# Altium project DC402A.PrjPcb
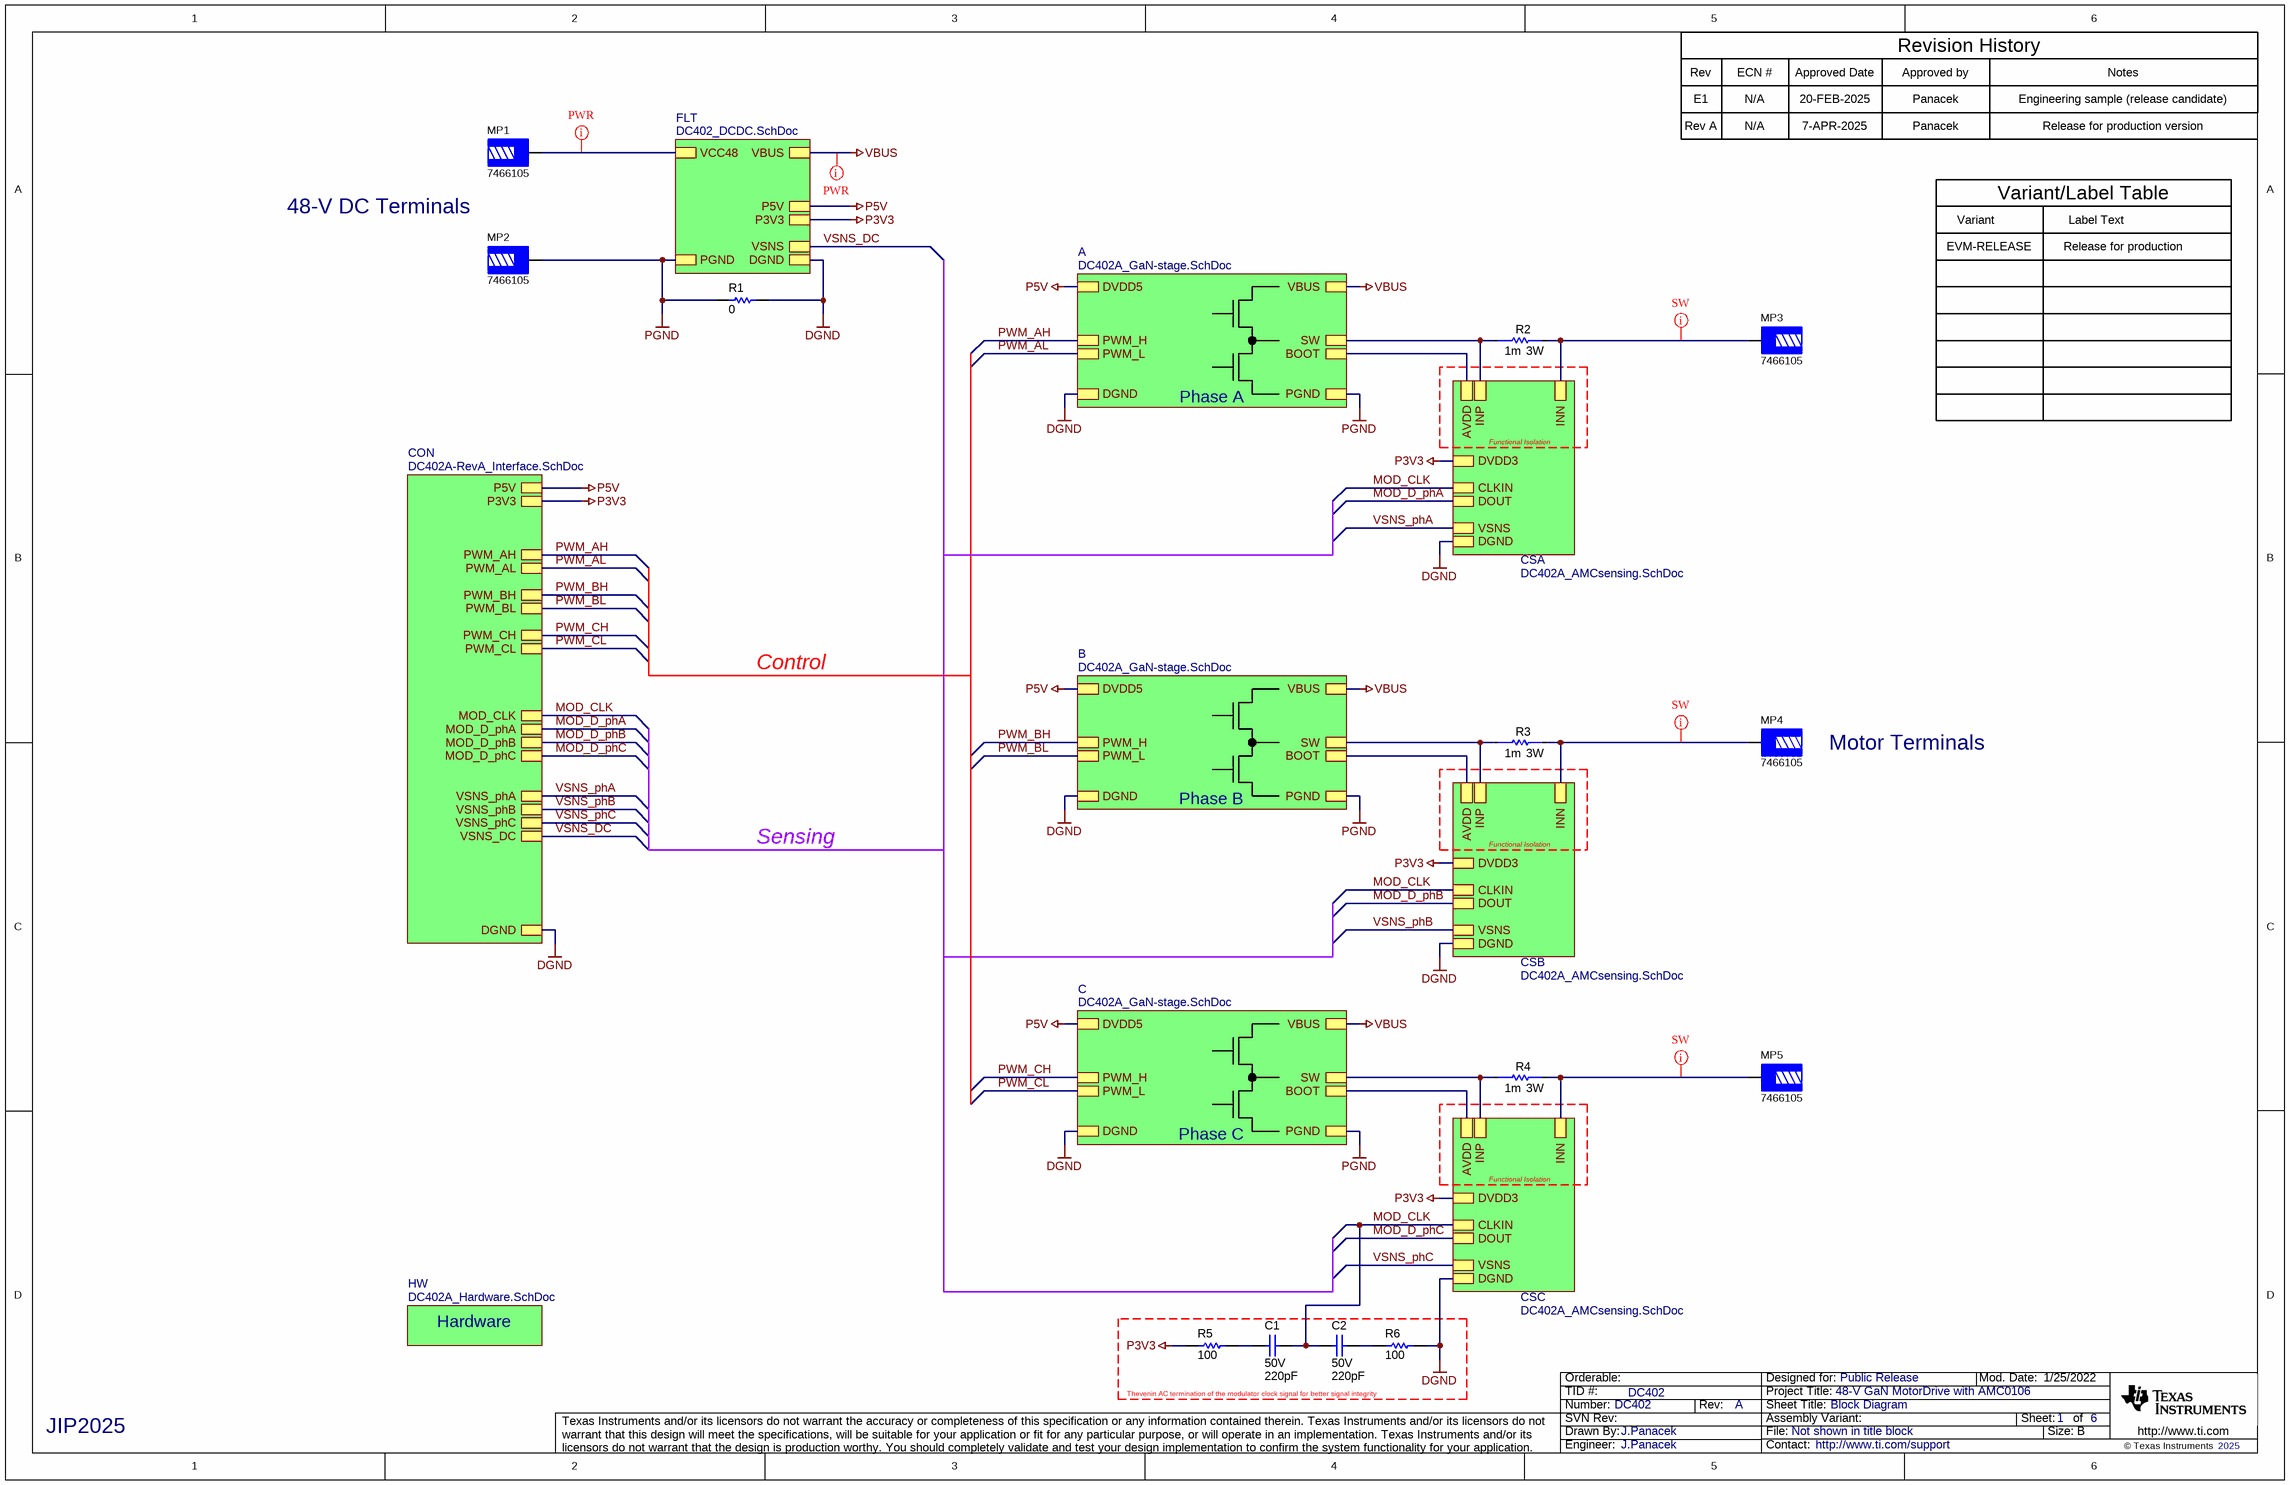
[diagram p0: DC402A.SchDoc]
CopyrightYear: 2025; PCB_Layout: J.Panacek; PCB_Rev: A; PRJ_Customer: Public Release; PRJ_Engineer: J.Panacek; PRJ_Number: DC402; PRJ_Title: 48-V GaN MotorDrive with AMC0106; SCH_Rev: A; TechSupport: http://www.ti.com/support; TID: DC402
6 sheets, 245 parts. Net scope: hierarchical (ports join the sheet entries above them; power ports are global).
Board file: DC402A.PcbDoc
Sheets:
  DC402A.SchDoc
    A = DC402A_GaN-stage.SchDoc
    CSA = DC402A_AMCsensing.SchDoc
    CON = DC402A-RevA_Interface.SchDoc
    FLT = DC402_DCDC.SchDoc
    B = DC402A_GaN-stage.SchDoc
    CSB = DC402A_AMCsensing.SchDoc
    C = DC402A_GaN-stage.SchDoc
    CSC = DC402A_AMCsensing.SchDoc
    HW = DC402A_Hardware.SchDoc

## Sheet DC402A.SchDoc: Block Diagram
size 431 x 279 mm; Date: Not shown in title block; ApprovedBy: Not shown in title block; CheckedBy: Not shown in title block; Author: Not shown in title block; CompanyName: Not shown in title block; DrawnBy: J.Panacek; Engineer: Not shown in title block; Organization: Not shown in title block; Address1: Not shown in title block; Address2: Not shown in title block; Address3: Not shown in title block; Address4: Not shown in title block; DocumentNumber: 1; Revision: Use project parameter SCH_Rev; SheetNumber: 1; SheetTotal: 6; PageSetup: Record=PageOptions¦CenterHorizontal=True¦CenterVertical=True¦PrintScale=1.00¦XCorrection=1.00¦YCorrection=1.00¦PrintKind=0¦BorderSize=5000000¦LeftOffset=0¦BottomOffset=0¦Orientation=2¦PaperLength=1000¦PaperWidth=1000¦Scale=100¦PaperSource=15¦PrintQuality=600¦MediaType=1¦DitherType=10¦PaperKind=Letter¦PrintScaleMode=1

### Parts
C1  VDC_V: 50V  ValueDisplayed: 220pF  [0603]  (hidden comment: GRM1885C1H221JA01D)
C2  VDC_V: 50V  ValueDisplayed: 220pF  [0603]  (hidden comment: GRM1885C1H221JA01D)
MP1  7466105  [7466105]
MP2  7466105  [7466105]
MP3  7466105  [7466105]
MP4  7466105  [7466105]
MP5  7466105  [7466105]
R1  ValueDisplayed: 0  [5106]  (hidden comment: 5106)
R2  value 1m  Power_W: 3W  [FP-ULRG32512R001FLFSLT_2512-MFG]  (hidden comment: ULRG32512R001FLFSLT)
R3  value 1m  Power_W: 3W  [FP-ULRG32512R001FLFSLT_2512-MFG]  (hidden comment: ULRG32512R001FLFSLT)
R4  value 1m  Power_W: 3W  [FP-ULRG32512R001FLFSLT_2512-MFG]  (hidden comment: ULRG32512R001FLFSLT)
R5  ValueDisplayed: 100  [0603]  (hidden comment: RC0603FR-07100RL)
R6  ValueDisplayed: 100  [0603]  (hidden comment: RC0603FR-07100RL)

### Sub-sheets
A = DC402A_GaN-stage.SchDoc: SW, VBUS, PGND, PWM_H, PWM_L, DGND, DVDD5, BOOT
B = DC402A_GaN-stage.SchDoc: SW, VBUS, PGND, PWM_H, PWM_L, DGND, DVDD5, BOOT
C = DC402A_GaN-stage.SchDoc: SW, VBUS, PGND, PWM_H, PWM_L, DGND, DVDD5, BOOT
CON = DC402A-RevA_Interface.SchDoc: PWM_AH, PWM_AL, PWM_BH, PWM_BL, PWM_CH, PWM_CL, MOD_CLK, MOD_D_phB, MOD_D_phA, MOD_D_phC, VSNS_phA, VSNS_phB, VSNS_phC, DGND, P5V, P3V3, VSNS_DC
CSA = DC402A_AMCsensing.SchDoc: INP, INN, CLKIN, DOUT, DVDD3, DGND, VSNS, AVDD
CSB = DC402A_AMCsensing.SchDoc: INP, INN, CLKIN, DOUT, DVDD3, DGND, VSNS, AVDD
CSC = DC402A_AMCsensing.SchDoc: INP, INN, CLKIN, DOUT, DVDD3, DGND, VSNS, AVDD
FLT = DC402_DCDC.SchDoc: VCC48, PGND, VBUS, P3V3, DGND, P5V, VSNS
HW = DC402A_Hardware.SchDoc: no entries

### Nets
DGND: R1.2 R6.2 ; sheet A/DGND, sheet CSA/DGND, sheet CON/DGND, sheet FLT/DGND, sheet B/DGND, sheet CSB/DGND, sheet C/DGND, sheet CSC/DGND
P3V3: R5.1 ; sheet CSA/DVDD3, sheet CON/P3V3, sheet FLT/P3V3, sheet CSB/DVDD3, sheet CSC/DVDD3
P5V: sheet A/DVDD5, sheet CON/P5V, sheet FLT/P5V, sheet B/DVDD5, sheet C/DVDD5
PGND: MP2.1 R1.1 ; sheet A/PGND, sheet FLT/PGND, sheet B/PGND, sheet C/PGND
VBUS: sheet A/VBUS, sheet FLT/VBUS, sheet B/VBUS, sheet C/VBUS
AVDD: sheet A/BOOT, sheet CSA/AVDD
AVDD: sheet B/BOOT, sheet CSB/AVDD  [a separate net that carries the same name]
AVDD: sheet C/BOOT, sheet CSC/AVDD  [a separate net that carries the same name]
INN: MP3.1 R2.2 ; sheet CSA/INN
INN: MP4.1 R3.2 ; sheet CSB/INN  [a separate net that carries the same name]
INN: MP5.1 R4.2 ; sheet CSC/INN  [a separate net that carries the same name]
INP: R2.1 ; sheet A/SW, sheet CSA/INP
INP: R3.1 ; sheet B/SW, sheet CSB/INP  [a separate net that carries the same name]
INP: R4.1 ; sheet C/SW, sheet CSC/INP  [a separate net that carries the same name]
MOD_CLK: C1.1 C2.2 ; sheet CSA/CLKIN, sheet CON/MOD_CLK, sheet CSB/CLKIN, sheet CSC/CLKIN
MOD_D_phA: sheet CSA/DOUT, sheet CON/MOD_D_phA
MOD_D_phB: sheet CON/MOD_D_phB, sheet CSB/DOUT
MOD_D_phC: sheet CON/MOD_D_phC, sheet CSC/DOUT
PWM_AH: sheet A/PWM_H, sheet CON/PWM_AH
PWM_AL: sheet A/PWM_L, sheet CON/PWM_AL
PWM_BH: sheet CON/PWM_BH, sheet B/PWM_H
PWM_BL: sheet CON/PWM_BL, sheet B/PWM_L
PWM_CH: sheet CON/PWM_CH, sheet C/PWM_H
PWM_CL: sheet CON/PWM_CL, sheet C/PWM_L
VCC48: MP1.1 ; sheet FLT/VCC48
VSNS_DC: sheet CON/VSNS_DC, sheet FLT/VSNS
VSNS_phA: sheet CSA/VSNS, sheet CON/VSNS_phA
VSNS_phB: sheet CON/VSNS_phB, sheet CSB/VSNS
VSNS_phC: sheet CON/VSNS_phC, sheet CSC/VSNS
NetC1_2: C1.2 R5.2
NetC2_1: C2.1 R6.1

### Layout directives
net class PWR: VBUS, VCC48
net class SW: INN

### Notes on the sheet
- Rev
- E1
- ECN #
- N/A
- Approved Date
- 20-FEB-2025
- Approved by
- Panacek
- Revision History
- Notes
- Engineering sample (release candidate)
- Rev A
- 7-APR-2025
- Release for production version
- 48-V DC Terminals
- Variant
- Variant/Label Table
- Label Text
- EVM-RELEASE
- Release for production
- Phase A
- Functional Isolation
- Control
- Motor Terminals
- Phase B
- Sensing
- Phase C
- Hardware
- JIP2025
- Thevenin AC termination of the modulator clock signal for better signal integrity

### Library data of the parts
C1 C2 = CMP-0007197-4: CAP, CERM, 220 pF, 50 V, +/- 5%, C0G/NP0, 0603; Manufacturer: MuRata; TaMin_C: -55°C; Polarized: N; SizeAreaWB_mm2: 4.68; Value1: Unknown; U/M: EA; Value: 220pF; TaMax_C: 125°C; SizeZ_mm: 1; SizeX_mm: 1.6; SizeY_mm: 0.8; SizeArea_mm2: 1.28; AEC Category: Q200
MP1-MP5 = CMP-03913-88496621-1: 7466105 WP-SMBU REDCUBE Bush, SMT_closed_pin; Current Rating: 70A; Number of Contacts: 1
R1 = CMP-0020833-2: RES, 0, 1%, 0.5 W, 0805; Manufacturer: Keystone; Power_W: 500mW; TempCo: ppm/C; U/M: EA; Value: 0; SizeX_mm: 2; SizeY_mm: 1.25; SizeZ_mm: 0.84; Value2: 0.5W; SizeArea_mm2: 2.5; AEC Qualified: N; AEC Category: Q200
R2-R4 = CMP-0042666-1: Res Metal Strip 2512 0.001 Ohm 1% 3W ±50ppm/C Pad SMD Automotive T/R; Manufacturer: TT Electronics; AEC Grade: Grade 0; AEC Qualified: Yes; SizeZ_mm: 0.8mm; TempCo: 50ppm/°C; TaMax_C: +170°C; TaMin_C: -55°C
R5 R6 = CMP-0022736-4: RES, 100, 1%, 0.1 W, 0603; Manufacturer: Yageo; Power_W: 100mW; TempCo: 100 ppm/C; Value_Code: 100R; Value: 100; EIA_Code: E96; SizeX_mm: 1.6; SizeY_mm: 0.8; SizeZ_mm: 1; Value2: 0.1W; SizeArea_mm2: 1.28; AEC Qualified: N; VDC_V: 75V; AEC Category: Q200; SizeAreaWB_mm2: 4.68

## Sheet DC402A_GaN-stage.SchDoc
size 431 x 279 mm; Date: Not shown in title block; ApprovedBy: Not shown in title block; CheckedBy: Not shown in title block; Author: Not shown in title block; CompanyName: Not shown in title block; Engineer: Not shown in title block; Organization: Not shown in title block; Address1: Not shown in title block; Address2: Not shown in title block; Address3: Not shown in title block; Address4: Not shown in title block; DocumentNumber: 2; Revision: Use project parameter SCH_Rev; SheetNumber: 2; SheetTotal: 6; PageSetup: Record=PageOptions¦CenterHorizontal=True¦CenterVertical=True¦PrintScale=1.00¦XCorrection=1.00¦YCorrection=1.00¦PrintKind=0¦BorderSize=5000000¦LeftOffset=0¦BottomOffset=0¦Orientation=2¦PaperLength=1000¦PaperWidth=1000¦Scale=100¦PaperSource=15¦PrintQuality=600¦MediaType=1¦DitherType=10¦PaperKind=Letter¦PrintScaleMode=1
Used 3 times, as channels A, B, C. Parts and nets are listed once, with the designators drawn on the sheet.
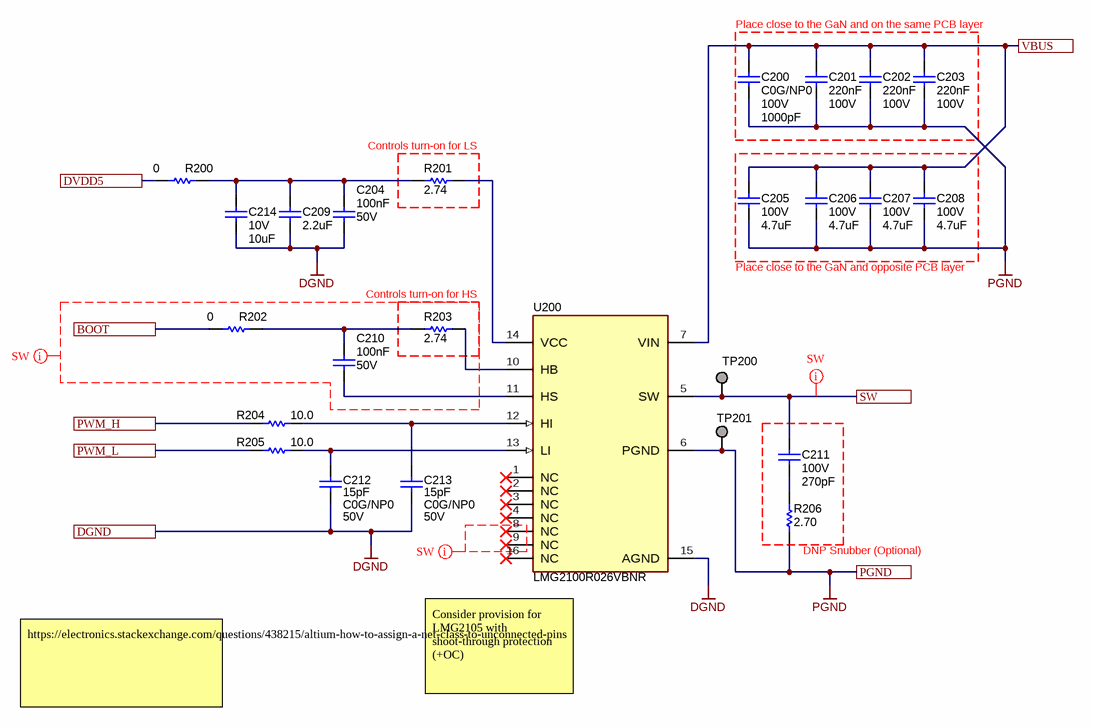
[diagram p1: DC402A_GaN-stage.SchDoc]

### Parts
C200  TempCo: C0G/NP0  VDC_V: 100V  ValueDisplayed: 1000pF  [0603]  (hidden comment: GRM1885C2A102JA01D)
C201  Cap_F: 220nF  VDC_V: 100V  [0805_HV]  (hidden comment: GRM21AR72A224KAC5L)
C202  Cap_F: 220nF  VDC_V: 100V  [0805_HV]  (hidden comment: GRM21AR72A224KAC5L)
C203  Cap_F: 220nF  VDC_V: 100V  [0805_HV]  (hidden comment: GRM21AR72A224KAC5L)
C204  Cap_F: 100nF  VDC_V: 50V  [0603]  (hidden comment: 885012206095)
C205  VDC_V: 100V  ValueDisplayed: 4.7uF  [1210_220]  (hidden comment: CGA6M3X7S2A475K200AB)
C206  VDC_V: 100V  ValueDisplayed: 4.7uF  [1210_220]  (hidden comment: CGA6M3X7S2A475K200AB)
C207  VDC_V: 100V  ValueDisplayed: 4.7uF  [1210_220]  (hidden comment: CGA6M3X7S2A475K200AB)
C208  VDC_V: 100V  ValueDisplayed: 4.7uF  [1210_220]  (hidden comment: CGA6M3X7S2A475K200AB)
C209  ValueDisplayed: 2.2uF  [0603]  (hidden comment: CGA3E3X5R1A225K080AB)
C210  Cap_F: 100nF  VDC_V: 50V  [0603]  (hidden comment: 885012206095)
C211  VDC_V: 100V  ValueDisplayed: 270pF  [0805_HV]  (hidden comment: GRM2165C2A271JA01D)
C212  Cap_F: 15pF  TempCo: C0G/NP0  VDC_V: 50V  [0603]  (hidden comment: 885012006052)
C213  Cap_F: 15pF  TempCo: C0G/NP0  VDC_V: 50V  [0603]  (hidden comment: 885012006052)
C214  VDC_V: 10V  ValueDisplayed: 10uF  [0603]  (hidden comment: GRM188C81A106MA73D)
R200  ValueDisplayed: 0  [0603]  (hidden comment: RC0603JR-070RL)
R201  ValueDisplayed: 2.74  [0603]  (hidden comment: RC0603FR-072R74L)
R202  ValueDisplayed: 0  [0603]  (hidden comment: RC0603JR-070RL)
R203  ValueDisplayed: 2.74  [0603]  (hidden comment: RC0603FR-072R74L)
R204  ValueDisplayed: 10.0  [0603]  (hidden comment: RC0603FR-0710RL)
R205  ValueDisplayed: 10.0  [0603]  (hidden comment: RC0603FR-0710RL)
R206  ValueDisplayed: 2.70  [1210]  (hidden comment: RC1210FR-072R7L)
TP200  TESTPOINT  [TP_VIA_060RND040]  (value not drawn)  (no BOM)
TP201  TESTPOINT  [TP_VIA_060RND040]  (value not drawn)  (no BOM)
U200  LMG2100R026VBNR  [VBN0016A-MFG]

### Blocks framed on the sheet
Place close to the GaN and on the same PCB layer: C200-C203
Controls turn-on for LS: R201
Controls turn-on for HS: R203

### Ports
BOOT, DGND, DVDD5, PGND, PWM_H, PWM_L, SW, VBUS

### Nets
DGND: C204.2 C209.2 C212.2 C213.2 C214.2 U200.15(AGND) ; port DGND
PGND: C200.2 C201.2 C202.2 C203.2 C205.2 C206.2 C207.2 C208.2 R206.1 TP201.1 U200.6(PGND) ; port PGND
BOOT: R202.1 ; port BOOT
DVDD5: R200.1 ; port DVDD5
PWM_H: R204.1 ; port PWM_H
PWM_L: R205.1 ; port PWM_L
SW: C211.1 TP200.1 U200.5(SW) ; port SW
VBUS: C200.1 C201.1 C202.1 C203.1 C205.1 C206.1 C207.1 C208.1 U200.7(VIN) ; port VBUS
NetC204_1: C204.1 C209.1 C214.1 R200.2 R201.1
NetC210_1: C210.1 R202.2 R203.1
NetC210_2: C210.2 U200.11(HS)
NetC211_2: C211.2 R206.2
NetC212_1: C212.1 R205.2 U200.13(LI)
NetC213_1: C213.1 R204.2 U200.12(HI)
NetR201_2: R201.2 U200.14(VCC)
NetR203_2: R203.2 U200.10(HB)

Not connected (* = marked no-connect by the designer): U200 1(NC)* 2(NC)* 3(NC)* 4(NC)* 8(NC)* 9(NC)* 16(NC)*

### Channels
A: designators end in _A; ports BOOT=AVDD DGND=DGND DVDD5=P5V PGND=PGND PWM_H=PWM_AH PWM_L=PWM_AL SW=INP VBUS=VBUS
B: designators end in _B; ports BOOT=AVDD DGND=DGND DVDD5=P5V PGND=PGND PWM_H=PWM_BH PWM_L=PWM_BL SW=INP VBUS=VBUS
C: designators end in _C; ports BOOT=AVDD DGND=DGND DVDD5=P5V PGND=PGND PWM_H=PWM_CH PWM_L=PWM_CL SW=INP VBUS=VBUS

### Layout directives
net class SW: (no net found under the mark), INP

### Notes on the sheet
- Place close to the GaN and opposite PCB layer
- (near R206) DNP Snubber (Optional)
- https://electronics.stackexchange.com/questions/438215/altium-how-to-assign-a-net-class-to-unconnected-pins
- (near U200) Consider provision for LMG2105 with shoot-through protection (+OC)

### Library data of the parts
C200 = CMP-0007238-4: CAP, CERM, 1000 pF, 100 V, +/- 5%, C0G/NP0, 0603; Manufacturer: MuRata; TaMin_C: -55°C; Polarized: N; SizeAreaWB_mm2: 4.68; Value1: Unknown; U/M: EA; Value: 1000pF; TaMax_C: 125°C; SizeZ_mm: 1; SizeX_mm: 1.6; SizeY_mm: 0.8; SizeArea_mm2: 1.28; Cap_F: 1nF; AEC Category: Q200
C201-C203 = CMP-0008249-2: CAP, CERM, 0.22 uF, 100 V, +/- 10%, X7R, 0805; Manufacturer: MuRata; TaMin_C: -55°C; Polarized: N; SizeAreaWB_mm2: 6.75; Value1: Unknown; U/M: EA; Value: 0.22uF; TaMax_C: 125°C; SizeZ_mm: 1.45; SizeX_mm: 2; SizeY_mm: 1.25; Cap_Case: 0805; SizeArea_mm2: 2.5; AEC Category: Q200
C204 C210 = CMP-0006837-4: CAP, CERM, 0.1 uF, 50 V, +/- 10%, X7R, 0603; Manufacturer: Wurth Elektronik; AEC Qualified: N; SizeZ_mm: 1; ValueDisplayed: 0.1uF; Value: 0.1uF; TaMin_C: -55°C; SizeAreaWB_mm2: 4.68; Value1: Unknown; U/M: EA; TaMax_C: 125°C; SizeX_mm: 1.6; SizeY_mm: 0.8; SizeArea_mm2: 1.28; AEC Category: Q200
C205-C208 = CMP-0009150-2: CAP, CERM, 4.7 uF, 100 V, +/- 10%, X7S, AEC-Q200 Grade 1, 1210; Manufacturer: TDK; TaMin_C: -55°C; ESR_ohm: 4.236m; Polarized: N; SizeAreaWB_mm2: 14.7; Value1: 0.004236 ohm; U/M: EA; Value: 4.7uF; TaMax_C: 125°C; SizeZ_mm: 2.2; SizeX_mm: 3.2; SizeY_mm: 2.5; SizeArea_mm2: 8; AEC Qualified: Y; Cap_F: 4.7µF; IRMS_A: 3.5734A; AEC Grade: 1; AEC Category: Q200
C209 = CMP-0007091-1: CAP, CERM, 2.2 uF, 10 V, +/- 10%, X5R, AEC-Q200 Grade 3, 0603; Manufacturer: TDK; TaMin_C: -55°C; Polarized: N; SizeAreaWB_mm2: 4.68; Value1: Unknown; U/M: EA; Value: 2.2uF; TaMax_C: 85°C; SizeZ_mm: 1; SizeX_mm: 1.6; SizeY_mm: 0.8; Value2: 10V; SizeArea_mm2: 1.28; AEC Qualified: Y; Cap_F: 2.2µF; AEC Grade: 3; AEC Category: Q200
C211 = CMP-0008113-2: CAP, CERM, 270 pF, 100 V, +/- 5%, C0G/NP0, 0805; Manufacturer: MuRata; TaMin_C: -55°C; Polarized: N; SizeAreaWB_mm2: 6.75; Value1: Unknown; U/M: EA; Value: 270pF; TaMax_C: 125°C; SizeZ_mm: 1.45; SizeX_mm: 2; SizeY_mm: 1.25; Cap_Case: 0805; SizeArea_mm2: 2.5; AEC Category: Q200
C212 C213 = CMP-0006821-4: CAP, CERM, 15 pF, 50 V, +/- 5%, C0G/NP0, 0603; Manufacturer: Wurth Elektronik; TaMin_C: -55°C; Polarized: N; SizeAreaWB_mm2: 4.68; Value1: Unknown; U/M: EA; Value: 15pF; TaMax_C: 125°C; SizeZ_mm: 1; SizeX_mm: 1.6; SizeY_mm: 0.8; SizeArea_mm2: 1.28; AEC Category: Q200
C214 = CMP-0007295-4: CAP, CERM, 10 uF, 10 V, +/- 20%, X6S, 0603; Manufacturer: MuRata; TaMin_C: -55°C; Polarized: N; SizeAreaWB_mm2: 4.68; Value1: Unknown; U/M: EA; Value: 10uF; TaMax_C: 105°C; SizeZ_mm: 1; SizeX_mm: 1.6; SizeY_mm: 0.8; SizeArea_mm2: 1.28; Cap_F: 10µF; AEC Category: Q200
R200 R202 = CMP-0025885-5: RES, 0, 5%, 0.1 W, 0603; Manufacturer: Yageo; AEC Qualified: N; SizeZ_mm: 1; Value: 0; Power_W: 100mW; TempCo: 200 ppm/C; Value_Code: 0000; EIA_Code: E24; SizeX_mm: 1.6; Value2: 0.1W; SizeArea_mm2: 1.28; VDC_V: 75V; AEC Category: Q200; SizeY_mm: 0.8; SizeAreaWB_mm2: 4.68
R201 R203 = CMP-0023010-4: RES, 2.74, 1%, 0.1 W, 0603; Manufacturer: Yageo; Power_W: 100mW; TempCo: 200 ppm/C; Value_Code: 2R74; Value: 2.74; EIA_Code: E96; SizeX_mm: 1.6; SizeY_mm: 0.8; SizeZ_mm: 1; Value2: 0.1W; SizeArea_mm2: 1.28; AEC Qualified: N; VDC_V: 75V; AEC Category: Q200; SizeAreaWB_mm2: 4.68
R204 R205 = CMP-0022751-4: RES, 10.0, 1%, 0.1 W, 0603; Manufacturer: Yageo; AEC Qualified: N; Res_ohm: 10; SizeZ_mm: 1; Value: 10.0; Power_W: 100mW; TempCo: 100 ppm/C; Value_Code: 10R0; EIA_Code: E96; SizeX_mm: 1.6; SizeY_mm: 0.8; Value2: 0.1W; SizeArea_mm2: 1.28; VDC_V: 75V; AEC Category: Q200; SizeAreaWB_mm2: 4.68
R206 = CMP-0083057-1: RES, 2.70, 1%, 0.5 W, 1210; Manufacturer: Yageo; Power_W: 500mW; TempCo: 200 ppm/C; SizeAreaWB_mm2: 14.7; Value_Code: 2R70; Value: 2.70; Res_ohm: 2.7; SizeX_mm: 3.2; SizeY_mm: 2.5; SizeZ_mm: 1.35; Value2: 0.5W; SizeArea_mm2: 8; AEC Qualified: N; VDC_V: 200V; AEC Category: Q200
TP200 TP201 = CMP-0078143-4: TEST POINT.  No entry in BOM.
U200 = CMP-0121493-2: 100-V, 53-A GaN Half-Bridge Power Stage; Manufacturer: Texas Instruments; SizeZ_mm: 0.85mm; AEC Qualified: No; Max Supply Voltage: 5.25V; Min Supply Voltage: 4.75V; Nominal Supply Current: 12mA; Number Of Drivers: 2; Number Of Outputs: 1; Propagation Delay: 29.5ns; Standoff Height: 0mm; TJmax_C: +150°C; AEC Category: Q200; CompType: IC

## Sheet DC402A_AMCsensing.SchDoc
size 431 x 279 mm; Date: Not shown in title block; ApprovedBy: Not shown in title block; CheckedBy: Not shown in title block; Author: Not shown in title block; CompanyName: Not shown in title block; Engineer: Not shown in title block; Organization: Not shown in title block; Address1: Not shown in title block; Address2: Not shown in title block; Address3: Not shown in title block; Address4: Not shown in title block; DocumentNumber: 1; Revision: Use project parameter SCH_Rev; SheetNumber: 4; SheetTotal: 6; PageSetup: Record=PageOptions¦CenterHorizontal=True¦CenterVertical=True¦PrintScale=1.00¦XCorrection=1.00¦YCorrection=1.00¦PrintKind=0¦BorderSize=5000000¦LeftOffset=0¦BottomOffset=0¦Orientation=2¦PaperLength=1000¦PaperWidth=1000¦Scale=100¦PaperSource=15¦PrintQuality=600¦MediaType=1¦DitherType=10¦PaperKind=Letter¦PrintScaleMode=1
Used 3 times, as channels CSA, CSB, CSC. Parts and nets are listed once, with the designators drawn on the sheet.
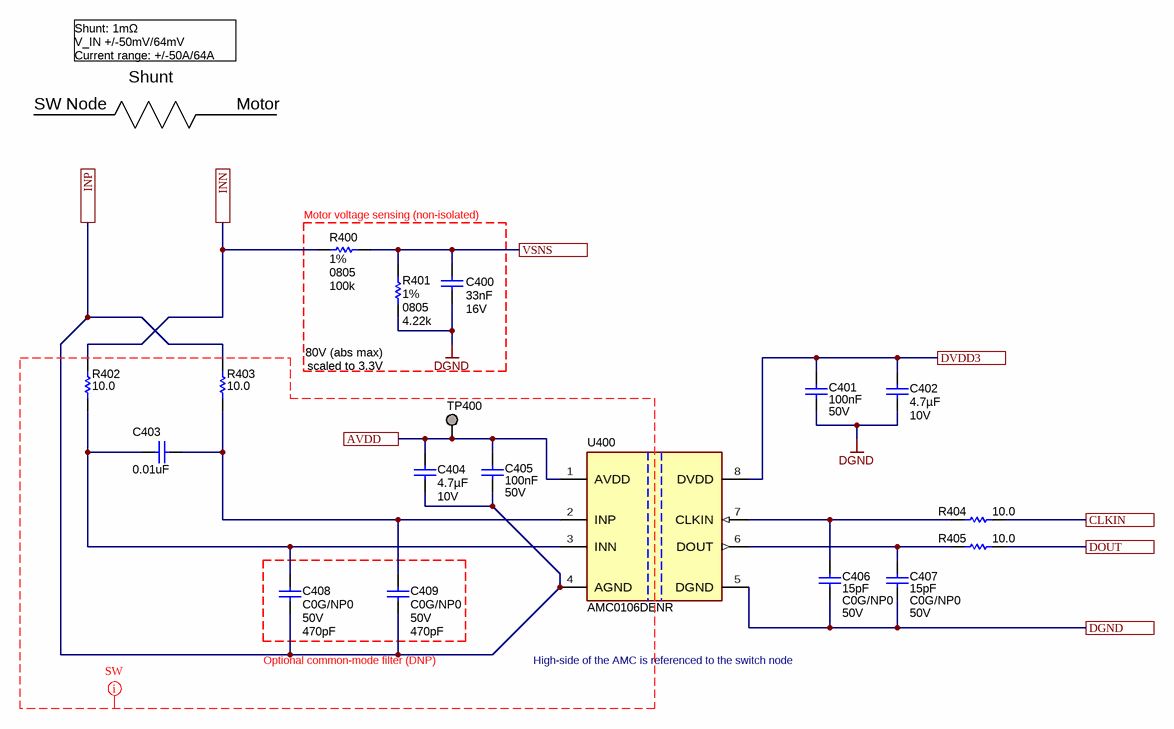
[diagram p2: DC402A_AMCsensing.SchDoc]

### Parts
C400  Cap_F: 33nF  Rated Voltage (DC): 16V  [WCAP-CSGP_0603_L1.6W0.8H0.8_Reflow]  (hidden comment: 885012206043)
C401  Cap_F: 100nF  VDC_V: 50V  [0603]  (hidden comment: 885012206095)
C402  Cap_F: 4.7µF  VDC_V: 10V  [0603]  (hidden comment: GRM188Z71A475ME15D)
C403  ValueDisplayed: 0.01uF  [0603]  (hidden comment: GRM1885C1H103JA01D)
C404  Cap_F: 4.7µF  VDC_V: 10V  [0603]  (hidden comment: GRM188Z71A475ME15D)
C405  Cap_F: 100nF  VDC_V: 50V  [0603]  (hidden comment: 885012206095)
C406  Cap_F: 15pF  TempCo: C0G/NP0  VDC_V: 50V  [0603]  (hidden comment: 885012006052)
C407  Cap_F: 15pF  TempCo: C0G/NP0  VDC_V: 50V  [0603]  (hidden comment: 885012006052)
C408  TempCo: C0G/NP0  VDC_V: 50V  ValueDisplayed: 470pF  [0603]  (hidden comment: GRM1885C1H471JA01D)
C409  TempCo: C0G/NP0  VDC_V: 50V  ValueDisplayed: 470pF  [0603]  (hidden comment: GRM1885C1H471JA01D)
R400  Value1: 1%  PackageReference: 0805  ValueDisplayed: 100k  [0805_HV]  (hidden comment: ERJ-6ENF1003V)
R401  Value1: 1%  PackageReference: 0805  ValueDisplayed: 4.22k  [0805_HV]  (hidden comment: ERJ-6ENF4221V)
R402  ValueDisplayed: 10.0  [0603]  (hidden comment: RC0603FR-0710RL)
R403  ValueDisplayed: 10.0  [0603]  (hidden comment: RC0603FR-0710RL)
R404  ValueDisplayed: 10.0  [0603]  (hidden comment: RC0603FR-0710RL)
R405  ValueDisplayed: 10.0  [0603]  (hidden comment: RC0603FR-0710RL)
TP400  TESTPOINT  [TP_VIA_060RND040]  (value not drawn)  (no BOM)
U400  AMC0106DENR  [DEN0008A-MFG]

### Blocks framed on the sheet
Motor voltage sensing (non-isolated): C400 R400 R401

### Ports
AVDD, CLKIN, DGND, DOUT, DVDD3, INN, INP, VSNS

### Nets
DGND: C400.1 C401.2 C402.2 R401.1
AVDD: C404.1 C405.1 TP400.1 U400.1(AVDD) ; port AVDD
CLKIN: R404.1 ; port CLKIN
DGND: C406.2 C407.2 U400.5(DGND) ; port DGND  [a separate net that carries the same name]
DOUT: R405.1 ; port DOUT
DVDD3: C401.1 C402.1 U400.8(DVDD) ; port DVDD3
INN: R400.1 R402.2 ; port INN
INP: C404.2 C405.2 C408.2 C409.2 R403.2 U400.4(AGND) ; port INP
VSNS: C400.2 R400.2 R401.2 ; port VSNS
NetC403_1: C403.1 C408.1 R402.1 U400.3(INN)
NetC403_2: C403.2 C409.1 R403.1 U400.2(INP)
NetC406_1: C406.1 R404.2 U400.7(CLKIN)
NetC407_1: C407.1 R405.2 U400.6(DOUT)

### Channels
CSA: designators end in _CSA; ports AVDD=AVDD CLKIN=MOD_CLK DGND=DGND DOUT=MOD_D_phA DVDD3=P3V3 INN=INN INP=INP VSNS=VSNS_phA
CSB: designators end in _CSB; ports AVDD=AVDD CLKIN=MOD_CLK DGND=DGND DOUT=MOD_D_phB DVDD3=P3V3 INN=INN INP=INP VSNS=VSNS_phB
CSC: designators end in _CSC; ports AVDD=AVDD CLKIN=MOD_CLK DGND=DGND DOUT=MOD_D_phC DVDD3=P3V3 INN=INN INP=INP VSNS=VSNS_phC

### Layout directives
net class SW: (no net found under the mark)

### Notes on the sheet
- Shunt: 1mΩ
  V_IN +/-50mV/64mV
  Current range: +/-50A/64A
- SW Node
- Shunt
- Motor
- (near R401) 80V (abs max) scaled to 3.3V
- Optional common-mode filter (DNP)
- High-side of the AMC is referenced to the switch node

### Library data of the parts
C400 = CMP-0119346-1: WCAP-CSGP Multilayer Ceramic Chip Capacitor, General Purpose, size 0603, X7R, 33nF, 16VDC; Manufacturer: Wurth Elektronik; Capacitance Tolerance: +/-10%; Case/Size Code: 0603; Dissipation Factor: 3.5%; Insulation Resistance: 10GOhm; Technical Reference: X7R0603333K016DFCT10000
C401 C405 = CMP-0006837-4: as C204 on sheet DC402A_GaN-stage
C402 C404 = CMP-0007498-4: CAP, CERM, 4.7 uF, 10 V, +/- 20%, X7R, 0603; Manufacturer: MuRata; TaMin_C: -55°C; Polarized: N; SizeAreaWB_mm2: 4.68; Value1: Unknown; U/M: EA; Value: 4.7uF; TaMax_C: 125°C; SizeZ_mm: 1; SizeX_mm: 1.6; SizeY_mm: 0.8; SizeArea_mm2: 1.28; AEC Category: Q200
C403 = CMP-0007174-4: CAP, CERM, 0.01 uF, 50 V, +/- 5%, C0G/NP0, 0603; Manufacturer: MuRata; Value: 0.01uF; Cap_F: 10nF; VDC_V: 50V; AEC Qualified: N; SizeZ_mm: 1; TaMin_C: -55°C; SizeAreaWB_mm2: 4.68; Value1: Unknown; U/M: EA; TaMax_C: 125°C; SizeX_mm: 1.6; SizeY_mm: 0.8; SizeArea_mm2: 1.28; AEC Category: Q200
C406 C407 = CMP-0006821-4: as C212 on sheet DC402A_GaN-stage
C408 C409 = CMP-0007221-4: CAP, CERM, 470 pF, 50 V, +/- 5%, C0G/NP0, 0603; Manufacturer: MuRata; TaMin_C: -55°C; Polarized: N; SizeAreaWB_mm2: 4.68; Value1: Unknown; U/M: EA; Value: 470pF; TaMax_C: 125°C; SizeZ_mm: 1; SizeX_mm: 1.6; SizeY_mm: 0.8; SizeArea_mm2: 1.28; AEC Category: Q200
R400 = CMP-0021521-3: RES, 100 k, 1%, 0.125 W, AEC-Q200 Grade 0, 0805; Manufacturer: Panasonic; Power_W: 125mW; TempCo: 100 ppm/C; Value: 100k; EIA_Code: E96; SizeX_mm: 2; SizeY_mm: 1.25; SizeZ_mm: 1.45; Value2: 0.125W; SizeArea_mm2: 2.5; AEC Qualified: Y; AEC Category: Q200; AEC Grade: 0; SizeAreaWB_mm2: 6.75
R401 = CMP-0021711-3: RES, 4.22 k, 1%, 0.125 W, AEC-Q200 Grade 0, 0805; Manufacturer: Panasonic; Power_W: 125mW; TempCo: 100 ppm/C; Value_Code: 4k22; Value: 4.22k; EIA_Code: E96; SizeX_mm: 2; SizeY_mm: 1.25; SizeZ_mm: 1.45; Value2: 0.125W; SizeArea_mm2: 2.5; AEC Qualified: Y; AEC Category: Q200; AEC Grade: 0; SizeAreaWB_mm2: 6.75
R402-R405 = CMP-0022751-4: as R204 on sheet DC402A_GaN-stage
TP400 = CMP-0078143-4: TEST POINT.  No entry in BOM.
U400 = CMP-0049066-2: ±50 mV Input Functionally Isolated Delta-Sigma Modulator for Current Sensing, VSON8; Manufacturer: Texas Instruments; SizeZ_mm: 1mm; Interface: SPI; Standoff Height: 0mm; AEC Category: Q200; CompType: IC

## Sheet DC402A-RevA_Interface.SchDoc
size 431 x 279 mm; Date: Not shown in title block; ApprovedBy: Not shown in title block; CheckedBy: Not shown in title block; Author: Not shown in title block; CompanyName: Not shown in title block; Engineer: Not shown in title block; Organization: Not shown in title block; Address1: Not shown in title block; Address2: Not shown in title block; Address3: Not shown in title block; Address4: Not shown in title block; DocumentNumber: 1; Revision: Use project parameter SCH_Rev; SheetNumber: 6; SheetTotal: 6; PageSetup: Record=PageOptions¦CenterHorizontal=True¦CenterVertical=True¦PrintScale=1.00¦XCorrection=1.00¦YCorrection=1.00¦PrintKind=0¦BorderSize=5000000¦LeftOffset=0¦BottomOffset=0¦Orientation=2¦PaperLength=1000¦PaperWidth=1000¦Scale=100¦PaperSource=15¦PrintQuality=600¦MediaType=1¦DitherType=10¦PaperKind=Letter¦PrintScaleMode=1
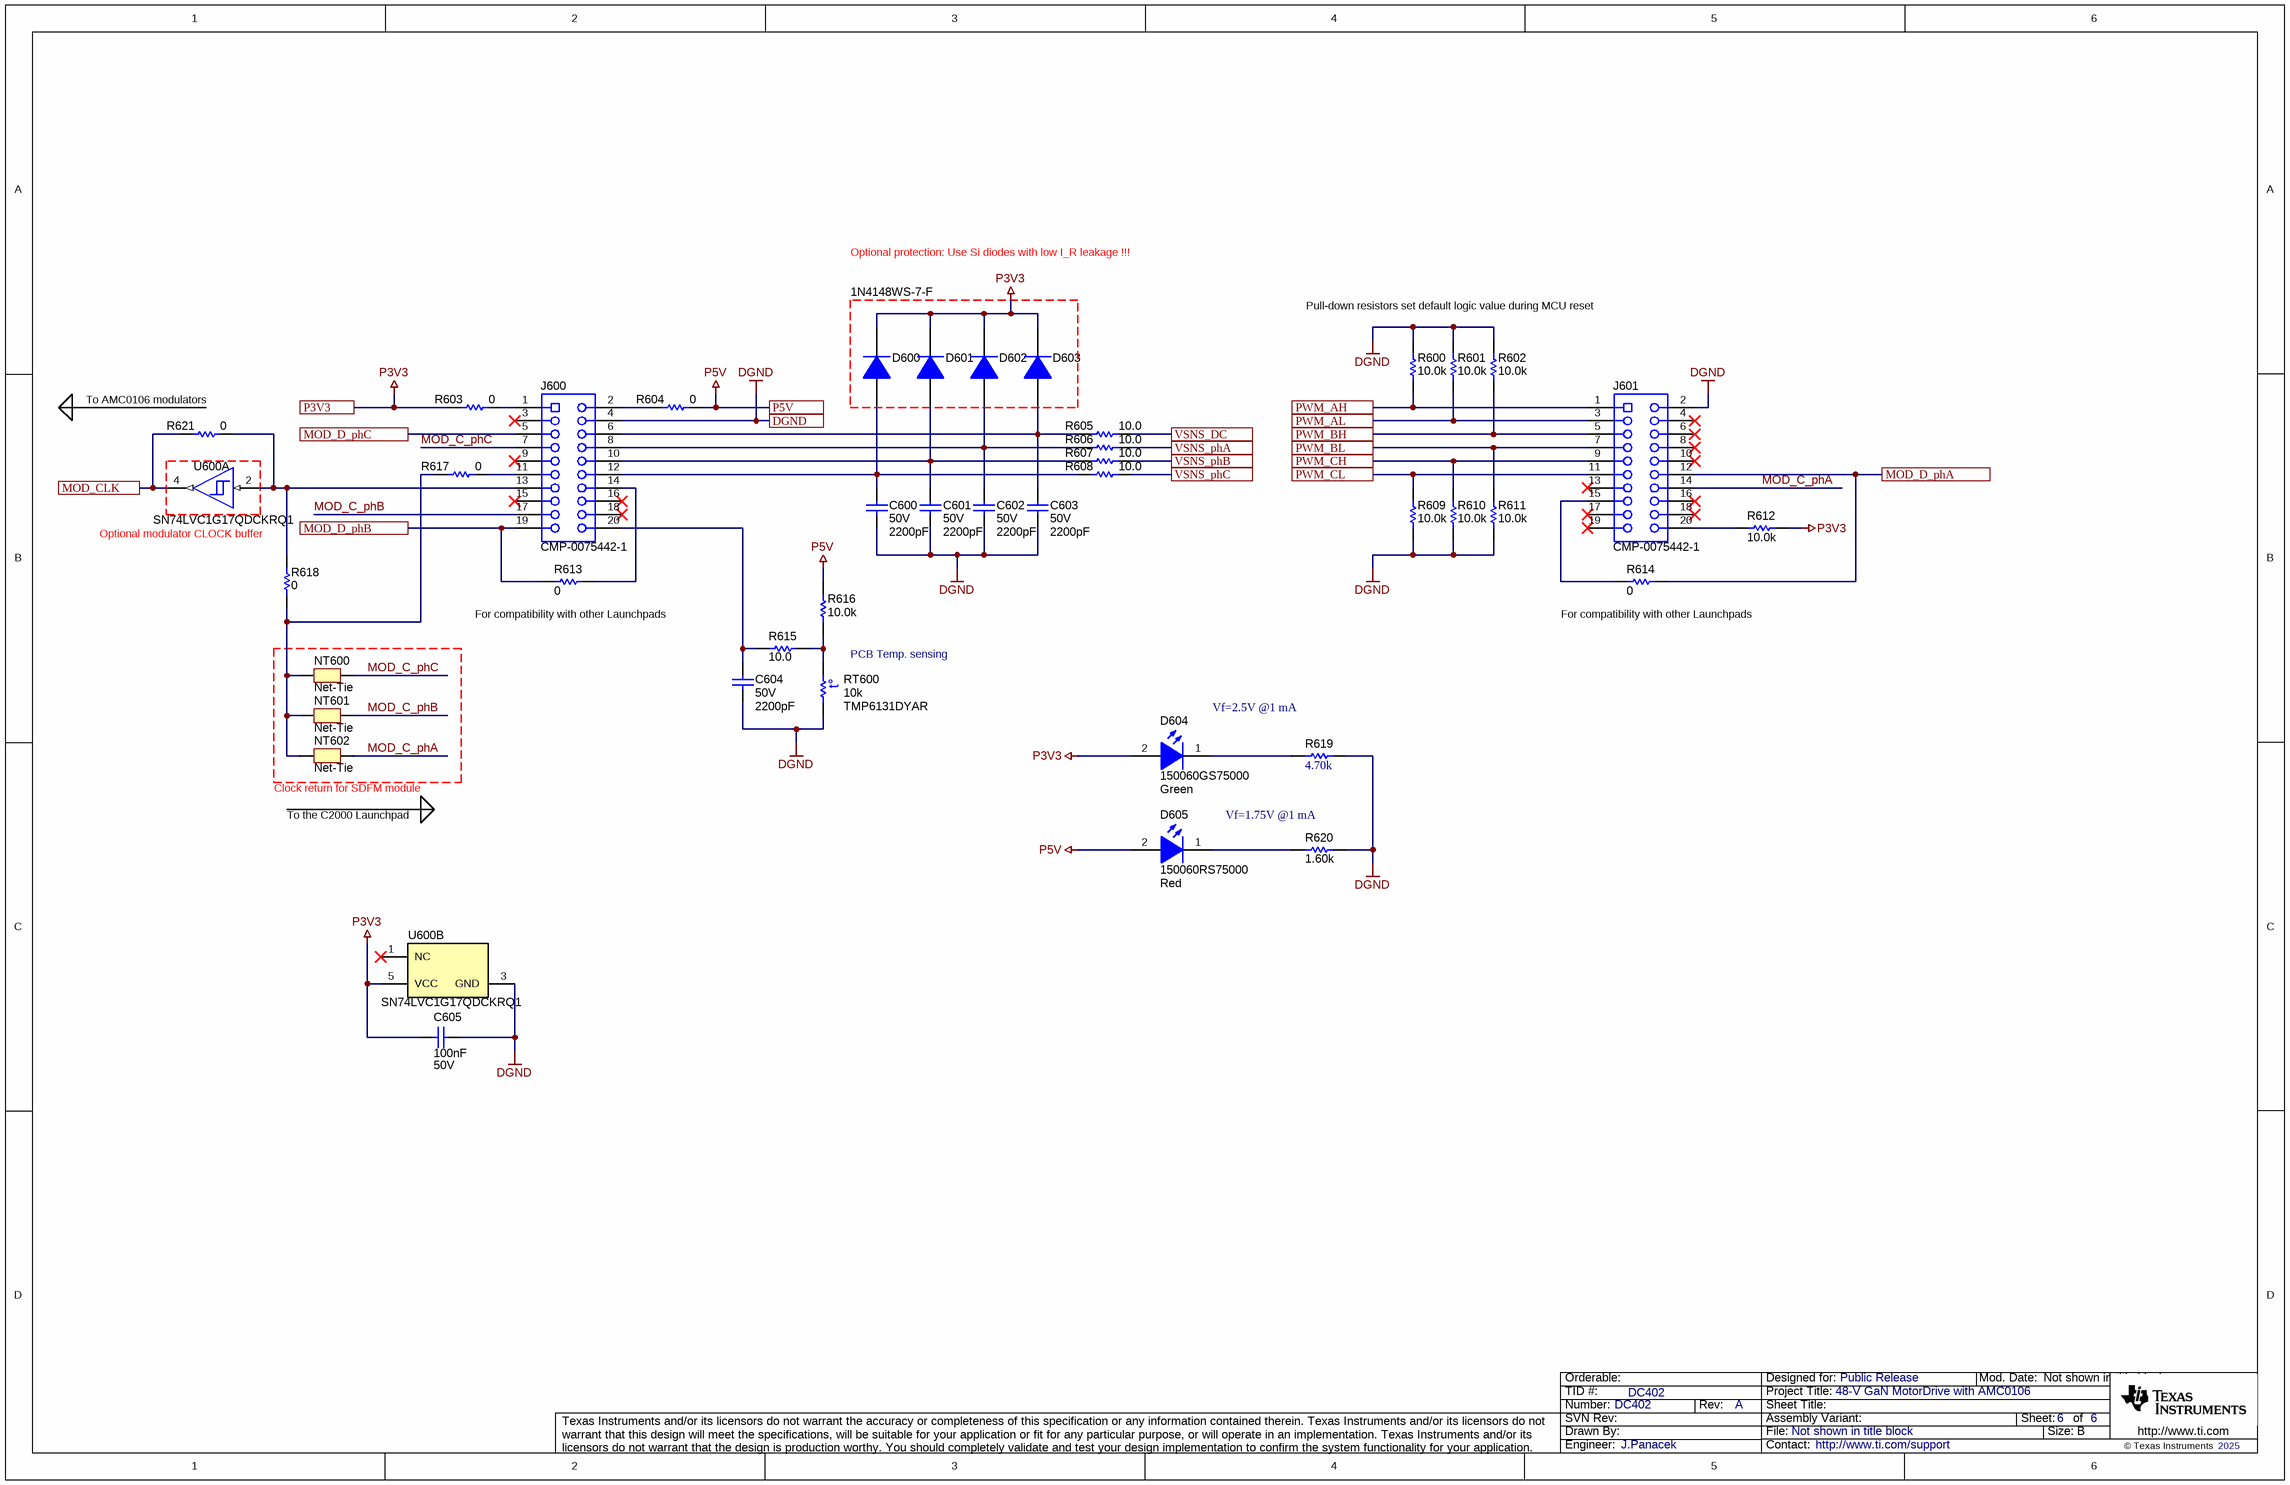
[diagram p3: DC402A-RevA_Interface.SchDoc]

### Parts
C600  VDC_V: 50V  ValueDisplayed: 2200pF  [0603]  (hidden comment: GRM1885C1H222JA01D)
C601  VDC_V: 50V  ValueDisplayed: 2200pF  [0603]  (hidden comment: GRM1885C1H222JA01D)
C602  VDC_V: 50V  ValueDisplayed: 2200pF  [0603]  (hidden comment: GRM1885C1H222JA01D)
C603  VDC_V: 50V  ValueDisplayed: 2200pF  [0603]  (hidden comment: GRM1885C1H222JA01D)
C604  VDC_V: 50V  ValueDisplayed: 2200pF  [0603]  (hidden comment: GRM1885C1H222JA01D)
C605  Cap_F: 100nF  VDC_V: 50V  [0603]  (hidden comment: 885012206095)
D600  1N4148WS-7-F  [SOD-323]
D601  1N4148WS-7-F  [SOD-323]  (value not drawn)
D602  1N4148WS-7-F  [SOD-323]  (value not drawn)
D603  1N4148WS-7-F  [SOD-323]  (value not drawn)
D604  150060GS75000  value Green  [WL-SMCW_GREEN]
D605  150060RS75000  value Red  [WL-SMCW_RED]
J600  CMP-0075442-1  [CONN_SSW-110-23-F-D]
J601  CMP-0075442-1  [CONN_SSW-110-23-F-D]
NT600  Net-Tie  [Net-Tie_10mil]  (net tie, no BOM)
NT601  Net-Tie  [Net-Tie_10mil]  (net tie, no BOM)
NT602  Net-Tie  [Net-Tie_10mil]  (net tie, no BOM)
R600  ValueDisplayed: 10.0k  [0603]  (hidden comment: RC0603FR-0710KL)
R601  ValueDisplayed: 10.0k  [0603]  (hidden comment: RC0603FR-0710KL)
R602  ValueDisplayed: 10.0k  [0603]  (hidden comment: RC0603FR-0710KL)
R603  ValueDisplayed: 0  [0603]  (hidden comment: PMR03EZPJ000)
R604  ValueDisplayed: 0  [0603]  (hidden comment: PMR03EZPJ000)
R605  ValueDisplayed: 10.0  [0603]  (hidden comment: RC0603FR-0710RL)
R606  ValueDisplayed: 10.0  [0603]  (hidden comment: RC0603FR-0710RL)
R607  ValueDisplayed: 10.0  [0603]  (hidden comment: RC0603FR-0710RL)
R608  ValueDisplayed: 10.0  [0603]  (hidden comment: RC0603FR-0710RL)
R609  ValueDisplayed: 10.0k  [0603]  (hidden comment: RC0603FR-0710KL)
R610  ValueDisplayed: 10.0k  [0603]  (hidden comment: RC0603FR-0710KL)
R611  ValueDisplayed: 10.0k  [0603]  (hidden comment: RC0603FR-0710KL)
R612  ValueDisplayed: 10.0k  [0603]  (hidden comment: RC0603FR-0710KL)
R613  ValueDisplayed: 0  [0603]  (hidden comment: PMR03EZPJ000)
R614  ValueDisplayed: 0  [0603]  (hidden comment: PMR03EZPJ000)
R615  ValueDisplayed: 10.0  [0603]  (hidden comment: RC0603FR-0710RL)
R616  ValueDisplayed: 10.0k  [0603]  (hidden comment: RC0603FR-0710KL)
R617  ValueDisplayed: 0  [0603]  (hidden comment: PMR03EZPJ000)
R618  ValueDisplayed: 0  [0603]  (hidden comment: PMR03EZPJ000)
R619  ValueDisplayed: 4.70k  [0603]  (hidden comment: RC0603FR-074K7L)
R620  ValueDisplayed: 1.60k  [0603]  (hidden comment: RC0603FR-071K6L)
R621  ValueDisplayed: 0  [0603]  (hidden comment: PMR03EZPJ000)
RT600  value 10k  [DYA0002A-MFG]  (hidden comment: TMP6131DYAR)
U600  SN74LVC1G17QDCKRQ1  [DCK0005A_N]  (parts A,B of 2)

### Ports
DGND, MOD_CLK, MOD_D_phA, MOD_D_phB, MOD_D_phC, P3V3, P5V, PWM_AH, PWM_AL, PWM_BH, PWM_BL, PWM_CH, PWM_CL, VSNS_DC, VSNS_phA, VSNS_phB, VSNS_phC

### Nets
DGND: C600.2 C601.2 C602.2 C603.2 C604.2 C605.2 J600.4 J601.2 R600.2 R601.2 R602.2 R609.1 R610.1 R611.1 R619.1 R620.1 RT600.1 U600.3(GND) ; port DGND
P3V3: C605.1 D600.1(K) D601.1(K) D602.1(K) D603.1(K) D604.2(A) R603.2 R612.1 U600.5(VCC) ; port P3V3
P5V: D605.2(A) R604.1 R616.2 ; port P5V
MOD_C_phA: J601.14 NT602.2
MOD_C_phB: J600.17 NT601.2
MOD_C_phC: J600.7 NT600.2
MOD_CLK: R621.2 U600.4(Y) ; port MOD_CLK
MOD_D_phA: J601.12 R614.1 ; port MOD_D_phA
MOD_D_phB: J600.19 R613.2 ; port MOD_D_phB
MOD_D_phC: J600.5 ; port MOD_D_phC
PWM_AH: J601.1 R600.1 ; port PWM_AH
PWM_AL: J601.3 R601.1 ; port PWM_AL
PWM_BH: J601.5 R602.1 ; port PWM_BH
PWM_BL: J601.7 R611.2 ; port PWM_BL
PWM_CH: J601.9 R610.2 ; port PWM_CH
PWM_CL: J601.11 R609.2 ; port PWM_CL
VSNS_DC: R605.2 ; port VSNS_DC
VSNS_phA: R606.2 ; port VSNS_phA
VSNS_phB: R607.2 ; port VSNS_phB
VSNS_phC: R608.2 ; port VSNS_phC
NetC600_1: C600.1 D600.2(A) J600.12 R608.1
NetC601_1: C601.1 D601.2(A) J600.10 R607.1
NetC602_1: C602.1 D602.2(A) J600.8 R606.1
NetC603_1: C603.1 D603.2(A) J600.6 R605.1
NetC604_1: C604.1 J600.20 R615.1
NetD604_1: D604.1(K) R619.2
NetD605_1: D605.1(K) R620.2
NetJ600_1: J600.1 R603.1
NetJ600_2: J600.2 R604.2
NetJ600_11: J600.11 R617.1
NetJ600_13: J600.13 R618.1 R621.1 U600.2(A)
NetJ600_14: J600.14 R613.1
NetJ601_15: J601.15 R614.2
NetJ601_20: J601.20 R612.2
NetNT600_1: NT600.1 NT601.1 NT602.1 R617.2 R618.2
NetR615_2: R615.2 R616.1 RT600.2

Not connected (* = marked no-connect by the designer): J600 3* 9* 15* 16* 18*; J601 4* 6* 8* 10* 13* 16* 17* 18* 19*; U600 1(NC)*

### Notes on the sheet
- Optional protection: Use Si diodes with low I_R leakage !!!
- Pull-down resistors set default logic value during MCU reset
- (near R621) To AMC0106 modulators
- Optional modulator CLOCK buffer
- (near R613) For compatibility with other Launchpads
- (near R614) For compatibility with other Launchpads
- PCB Temp. sensing
- Vf=2.5V @1 mA
- (near NT602) Clock return for SDFM module
- To the C2000 Launchpad
- (near R620) Vf=1.75V @1 mA

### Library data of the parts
C600-C604 = CMP-0007198-2: CAP, CERM, 2200 pF, 50 V, +/- 5%, C0G/NP0, 0603; Manufacturer: MuRata; TaMin_C: -55°C; Polarized: N; SizeAreaWB_mm2: 4.68; Value1: Unknown; U/M: EA; Value: 2200pF; TaMax_C: 125°C; SizeZ_mm: 1; SizeX_mm: 1.6; SizeY_mm: 0.8; SizeArea_mm2: 1.28; Cap_F: 2.2nF; AEC Category: Q200
C605 = CMP-0006837-4: as C204 on sheet DC402A_GaN-stage
D600-D603 = CMP-0079597-2: Diode, Switching, 75 V, 0.15 A, AEC-Q101, SOD-323; Manufacturer: Diodes Inc.; SizeX_mm: 2.7; Vf_V: 1.25V; AEC Qualified: Y; SizeArea_mm2: 3.645; AEC Category: Q101; SizeAreaWB_mm2: 8.695; Io_A: 150mA; SizeZ_mm: 1; Value1: 0.15A; SizeY_mm: 1.35; TJmax_C: 150°C; Vr_V: 75V; Value: 75V
D604 = CMP-0002905-1: LED, Green, SMD; Manufacturer: Wurth Elektronik; Io_A: 20mA; Tjmax_C: 85°C; Value1: W; U/M: EA; Angle: 140; Vf_V: 3.2V; Type: InGaN
D605 = CMP-0002947-3: LED, Red, SMD; Manufacturer: Wurth Elektronik; Value1: 0.072W; Vf_V: 2V; Angle: 140; Tjmax_C: 85°C; Type: AlInGaP; Vr_V: 5V; Io_A: 30mA; Power_TotalModule: 72mW
J600 J601 = CMP-0075442-1: Connector, Receptacle, 100mil, 10x2, Gold plated, TH; PartNumber: SSW-110-23-F-D; Manufacturer: Samtec; CompType: Socket Strip; Green_Lifecycle: Active; Green_REACh: Passed; CT: True; CNHeader: False
NT600-NT602 = CMP-0078142-2: Single point connection between nets.
R600-R602 R609-R612 R616 = CMP-0022746-5: RES, 10.0 k, 1%, 0.1 W, 0603; Manufacturer: Yageo; Power_W: 100mW; TempCo: 100 ppm/C; Value_Code: 10k0; Value: 10.0k; EIA_Code: E96; Res_ohm: 10k; SizeX_mm: 1.6; SizeY_mm: 0.8; SizeZ_mm: 1; Value2: 0.1W; SizeArea_mm2: 1.28; AEC Qualified: N; VDC_V: 75V; AEC Category: Q200; SizeAreaWB_mm2: 4.68
R603 R604 R613 R614 R617 R618 R621 = CMP-0086358-1: RES, 0, 0%, 0.25 W, AEC-Q200 Grade 0, 0603; Manufacturer: Rohm; Power_W: 250mW; SizeZ_mm: 1; SizeArea_mm2: 1.28; Value2: 0.25W; SizeAreaWB_mm2: 4.68; Value_Code: 0000; Value: 0; AEC Qualified: Y; AEC Category: Q200; SizeX_mm: 1.6; SizeY_mm: 0.8
R605-R608 R615 = CMP-0022751-4: as R204 on sheet DC402A_GaN-stage
R619 = CMP-0023153-5: RES, 4.70 k, 1%, 0.1 W, 0603; Manufacturer: Yageo; Power_W: 100mW; TempCo: 100 ppm/C; Value_Code: 4k70; Value: 4.70k; Res_ohm: 4.7k; SizeX_mm: 1.6; SizeY_mm: 0.8; SizeZ_mm: 1; Value2: 0.1W; SizeArea_mm2: 1.28; AEC Qualified: N; VDC_V: 75V; AEC Category: Q200; SizeAreaWB_mm2: 4.68
R620 = CMP-0022887-5: RES, 1.60 k, 1%, 0.1 W, 0603; Manufacturer: Yageo; Power_W: 100mW; TempCo: 100 ppm/C; Value_Code: 1k60; Value: 1.60k; Res_ohm: 1.6k; SizeX_mm: 1.6; SizeY_mm: 0.8; SizeZ_mm: 1; Value2: 0.1W; SizeArea_mm2: 1.28; AEC Qualified: N; VDC_V: 75V; AEC Category: Q200; SizeAreaWB_mm2: 4.68
RT600 = CMP-0126259-2: 1%, 10-kΩ linear thermistor in 0402, 0603/0805 and through hole packages 2-SOT-5X3 -40 to 125; Manufacturer: Texas Instruments; Max Current: 400uA; AEC Qualified: No; TJmax_C: +155°C; TaMin_C: -40°C; Res_ohm: 10kΩ; TempCo: 6400ppm/°C; TaMax_C: +125°C; VDC_V: 5.5V; SizeZ_mm: 0.77mm; AEC Category: Q200; CompType: IC
U600 = CMP-0051710-3: Automotive Catalog Single Schmitt-Trigger Buffer, DCK0005A, LARGE T&R; Manufacturer: Texas Instruments; Generic Part Number: SN74LVC1G17-Q1; F @ Nom Voltage(Max)(Mhz): 150; Bits(#): 1; Schmitt Trigger: Yes; Sub-Family: Non-Inverting Buffer/Driver; Output Type: CMOS; Technology Family: LVC; Voltage(Nom)(V): 1.8,2.5,3.3,5; Logic: True; Input Type: CMOS/TTL; VCC(Min)(V): 1.65; Output Drive (IOL/IOH)(Max)(mA): 32/-32; VCC(Max)(V): 6.5; tpd @ Nom Voltage(Max)(ns): 14,9,8,7; ICC @ Nom Voltage(Max)(mA): 0.02; 3-State Output: No; AEC Category: Q200; AEC Qualified: Y; CompType: IC; SizeAreaWB_mm2: 9.3; SizeArea_mm2: 4.2; SizeX_mm: 2.1; SizeY_mm: 2.0; SizeZ_mm: 1.1

## Sheet DC402_DCDC.SchDoc
size 431 x 279 mm; Date: Not shown in title block; ApprovedBy: Not shown in title block; CheckedBy: Not shown in title block; Author: Not shown in title block; CompanyName: Not shown in title block; Engineer: Not shown in title block; Organization: Not shown in title block; Address1: Not shown in title block; Address2: Not shown in title block; Address3: Not shown in title block; Address4: Not shown in title block; DocumentNumber: 1; Revision: Use project parameter SCH_Rev; SheetNumber: 5; SheetTotal: 6; PageSetup: Record=PageOptions¦CenterHorizontal=True¦CenterVertical=True¦PrintScale=1.00¦XCorrection=1.00¦YCorrection=1.00¦PrintKind=0¦BorderSize=5000000¦LeftOffset=0¦BottomOffset=0¦Orientation=2¦PaperLength=1000¦PaperWidth=1000¦Scale=100¦PaperSource=15¦PrintQuality=600¦MediaType=1¦DitherType=10¦PaperKind=Letter¦PrintScaleMode=1
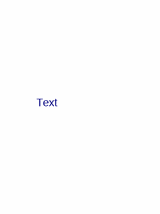
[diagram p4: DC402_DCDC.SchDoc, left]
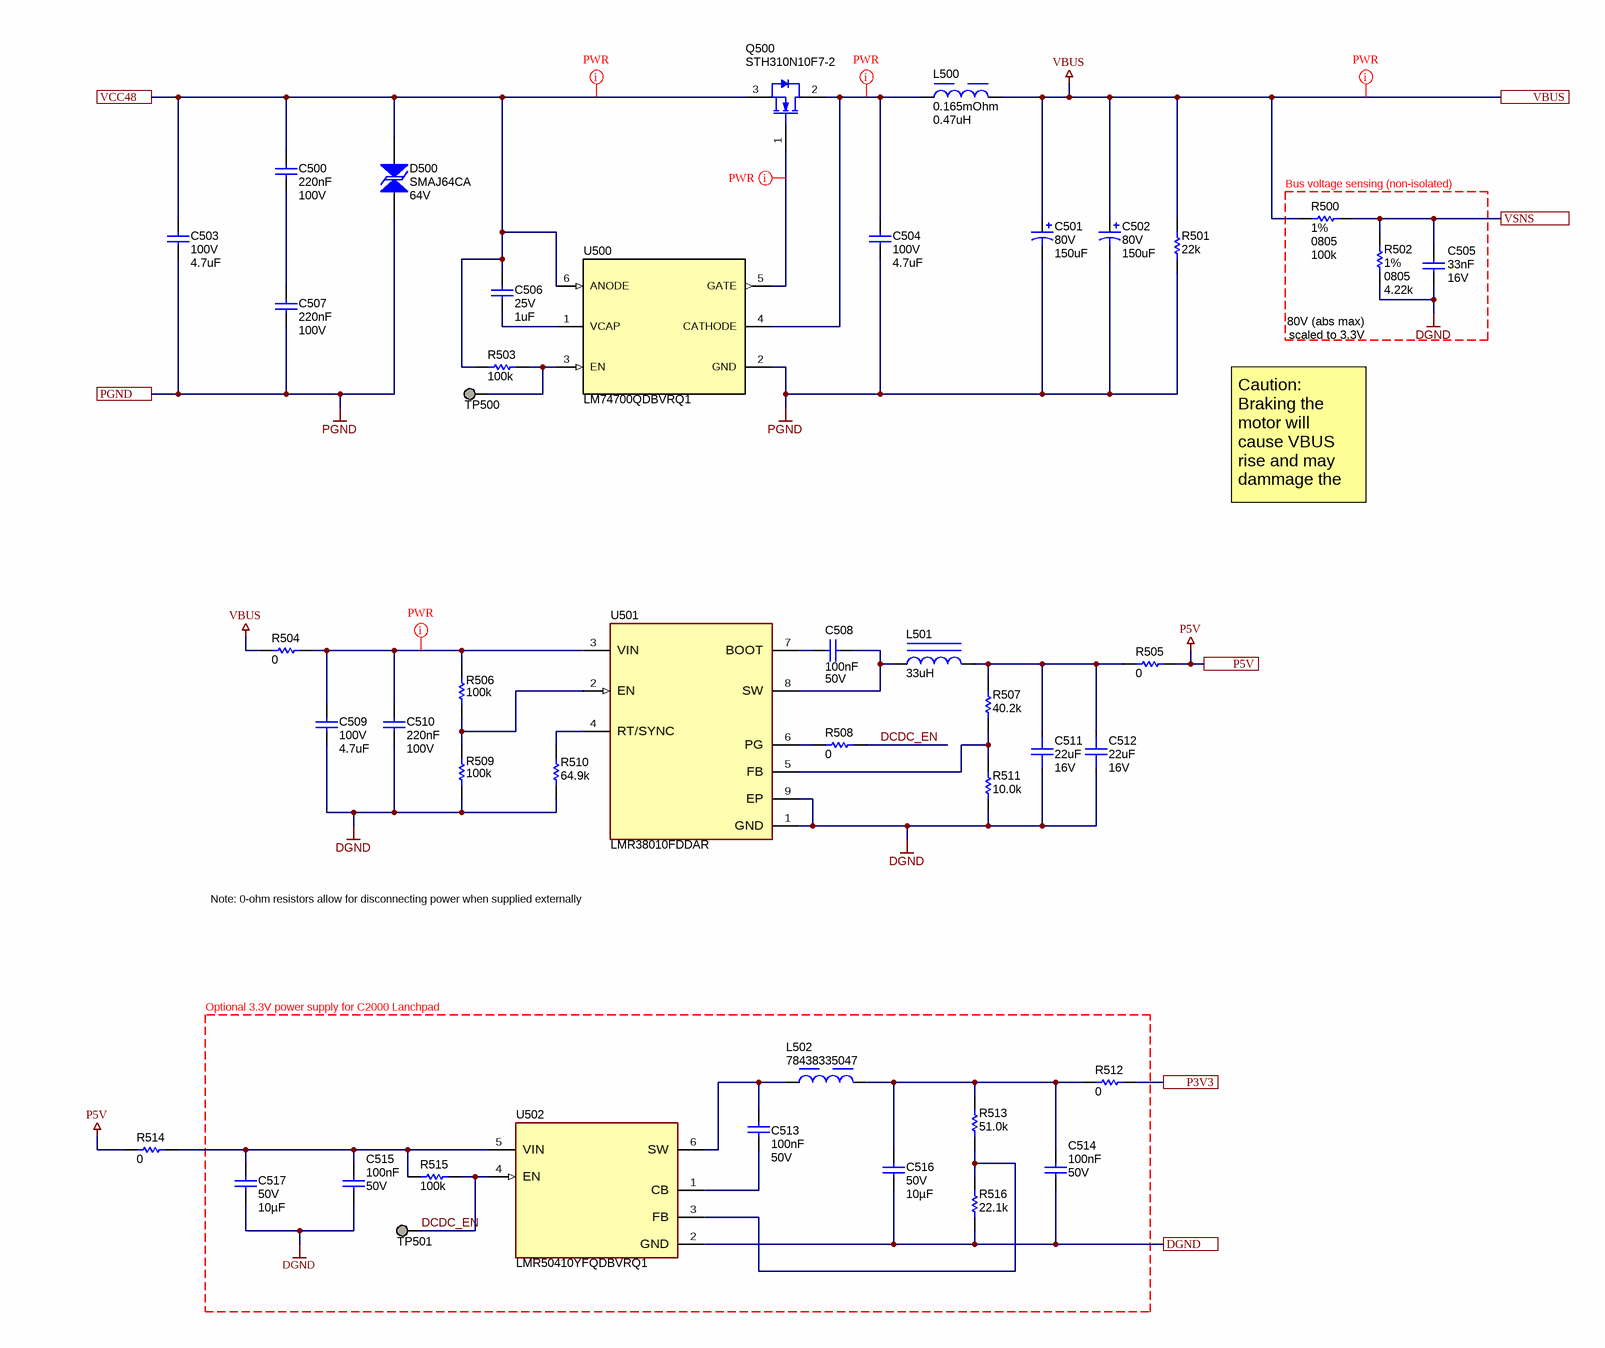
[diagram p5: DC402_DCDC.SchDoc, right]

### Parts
C500  Cap_F: 220nF  VDC_V: 100V  [0805_HV]  (hidden comment: GRM21AR72A224KAC5L)
C501  VDC_V: 80V  ValueDisplayed: 150uF  [UCZ_1250x1350]  (hidden comment: UCZ1K151MNQ1MS)
C502  VDC_V: 80V  ValueDisplayed: 150uF  [UCZ_1250x1350]  (hidden comment: UCZ1K151MNQ1MS)
C503  VDC_V: 100V  ValueDisplayed: 4.7uF  [1210_220]  (hidden comment: CGA6M3X7S2A475K200AB)
C504  VDC_V: 100V  ValueDisplayed: 4.7uF  [1210_220]  (hidden comment: CGA6M3X7S2A475K200AB)
C505  Cap_F: 33nF  Rated Voltage (DC): 16V  [WCAP-CSGP_0603_L1.6W0.8H0.8_Reflow]  (hidden comment: 885012206043)
C506  VDC_V: 25V  ValueDisplayed: 1uF  [0603]  (hidden comment: GRM188R61E105KA12D)
C507  Cap_F: 220nF  VDC_V: 100V  [0805_HV]  (hidden comment: GRM21AR72A224KAC5L)
C508  Cap_F: 100nF  VDC_V: 50V  [0603]  (hidden comment: 885012206095)
C509  VDC_V: 100V  ValueDisplayed: 4.7uF  [1210_220]  (hidden comment: CGA6M3X7S2A475K200AB)
C510  Cap_F: 220nF  VDC_V: 100V  [0805_HV]  (hidden comment: GRM21AR72A224KAC5L)
C511  ValueDisplayed: 22uF  VDC_V: 16V  [FP-GRM31CZ71C226ME15L_1206-MFG]  (hidden comment: GRM31CZ71C226ME15L)
C512  ValueDisplayed: 22uF  VDC_V: 16V  [FP-GRM31CZ71C226ME15L_1206-MFG]  (hidden comment: GRM31CZ71C226ME15L)
C513  Cap_F: 100nF  VDC_V: 50V  [0603]  (hidden comment: 885012206095)
C514  Cap_F: 100nF  VDC_V: 50V  [0603]  (hidden comment: 885012206095)
C515  Cap_F: 100nF  VDC_V: 50V  [0603]  (hidden comment: 885012206095)
C516  VDC_V: 50V  ValueDisplayed: 10µF  [1206_180]  (hidden comment: 885012108022)
C517  VDC_V: 50V  ValueDisplayed: 10µF  [1206_180]  (hidden comment: 885012108022)
D500  SMAJ64CA  value 64V  [SMA_Bi]
L500  DC Resistance: 0.165mOhm  Inductance: 0.47uH  [WE-HCM_1390_L12.5W13H9]  (hidden comment: 744309047)
L501  ValueDisplayed: 33uH  [WE-PD_7332_PlasticBase]  (hidden comment: 7447789133)
L502  78438335047  [WE-MAIA_3015]
Q500  STH310N10F7-2  [DDPAK]
R500  Value1: 1%  PackageReference: 0805  ValueDisplayed: 100k  [0805_HV]  (hidden comment: ERJ-6ENF1003V)
R501  ValueDisplayed: 22k  [1210]  (hidden comment: RC1210JR-0722KL)
R502  Value1: 1%  PackageReference: 0805  ValueDisplayed: 4.22k  [0805_HV]  (hidden comment: ERJ-6ENF4221V)
R503  ValueDisplayed: 100k  [0603]  (hidden comment: RC0603FR-07100KL)
R504  ValueDisplayed: 0  [0603]  (hidden comment: PMR03EZPJ000)
R505  ValueDisplayed: 0  [0603]  (hidden comment: PMR03EZPJ000)
R506  ValueDisplayed: 100k  [0603]  (hidden comment: RC0603FR-07100KL)
R507  ValueDisplayed: 40.2k  [0603]  (hidden comment: RC0603FR-0740K2L)
R508  ValueDisplayed: 0  [0603]  (hidden comment: PMR03EZPJ000)
R509  ValueDisplayed: 100k  [0603]  (hidden comment: RC0603FR-07100KL)
R510  ValueDisplayed: 64.9k  [0603]  (hidden comment: RC0603FR-0764K9L)
R511  ValueDisplayed: 10.0k  [0603]  (hidden comment: RC0603FR-0710KL)
R512  ValueDisplayed: 0  [0603]  (hidden comment: PMR03EZPJ000)
R513  ValueDisplayed: 51.0k  [0603]  (hidden comment: RC0603FR-0751KL)
R514  ValueDisplayed: 0  [0603]  (hidden comment: PMR03EZPJ000)
R515  ValueDisplayed: 100k  [0603]  (hidden comment: RC0603FR-07100KL)
R516  ValueDisplayed: 22.1k  [0603]  (hidden comment: RC0603FR-0722K1L)
TP500  TESTPOINT  [TP_60MIL-SMT]  (value not drawn)  (no BOM)
TP501  TESTPOINT  [TP_50MIL-25MILHOLE]  (value not drawn)  (no BOM)
U500  LM74700QDBVRQ1  [DBV0006A_N]
U501  LMR38010FDDAR  [DDA0008E-MFG]
U502  LMR50410YFQDBVRQ1  [DBV0006A-MFG]

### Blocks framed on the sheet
Bus voltage sensing (non-isolated): C505 R500 R502
Optional 3.3V power supply for C2000 Lanchpad: C513-C517 L502 R512 R513 R515 R516 TP501 U502

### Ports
DGND, P3V3, P5V, PGND, VBUS, VCC48, VSNS

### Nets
DGND: C505.1 C509.2 C510.2 C511.1 C512.1 C514.2 C515.2 C516.2 C517.2 R502.1 R509.2 R510.1 R511.1 R516.1 U501.1(GND) U501.9(EP) U502.2(GND) ; port DGND
P3V3: R512.1 ; port P3V3
P5V: R505.1 R514.2 ; port P5V
PGND: C501.2(-) C502.2(-) C503.2 C504.2 C507.2 D500.1 R501.1 U500.2(GND) ; port PGND
VBUS: C501.1(+) C502.1(+) L500.2 R500.1 R501.2 R504.2 ; port VBUS
DCDC_EN: R508.1 R515.1 TP501.1 U502.4(EN)
VCC48: C500.1 C503.1 C506.1 D500.2 Q500.3(S) R503.2 U500.6(ANODE) ; port VCC48
VSNS_DC: C505.2 R500.2 R502.2 ; port VSNS
NetC500_2: C500.2 C507.1
NetC504_1: C504.1 L500.1 Q500.2(D) U500.4(CATHODE)
NetC506_2: C506.2 U500.1(VCAP)
NetC508_1: C508.1 U501.7(BOOT)
NetC508_2: C508.2 L501.1 U501.8(SW)
NetC509_1: C509.1 C510.1 R504.1 R506.1 U501.3(VIN)
NetC511_2: C511.2 C512.2 L501.2 R505.2 R507.2
NetC513_1: C513.1 U502.1(CB)
NetC513_2: C513.2 L502.1 U502.6(SW)
NetC514_1: C514.1 C516.1 L502.2 R512.2 R513.2
NetC515_1: C515.1 C517.1 R514.1 R515.2 U502.5(VIN)
NetQ500_1: Q500.1(G) U500.5(GATE)
NetR503_1: R503.1 TP500.1 U500.3(EN)
NetR506_2: R506.2 R509.1 U501.2(EN)
NetR507_1: R507.1 R511.2 U501.5(FB)
NetR508_2: R508.2 U501.6(PG)
NetR510_2: R510.2 U501.4(RT/SYNC)
NetR513_1: R513.1 R516.2 U502.3(FB)

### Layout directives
net class PWR: NetC504_1, NetC509_1, NetQ500_1, VBUS, VCC48

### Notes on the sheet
- (near R502) 80V (abs max) scaled to 3.3V
- Caution: Braking the motor will cause VBUS rise and may dammage the system!
- Note: 0-ohm resistors allow for disconnecting power when supplied externally
- Text

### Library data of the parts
C500 C507 C510 = CMP-0008249-2: as C201 on sheet DC402A_GaN-stage
C501 C502 = CMP-0011411-2: CAP, AL, 150 uF, 80 V, +/- 20%, 0.2 ohm, AEC-Q200 Grade 1, SMD; Manufacturer: Nichicon; TaMin_C: -40°C; ESR_ohm: 0.2; Polarized: Y; SizeAreaWB_mm2: 258.96; Value1: 0.2 ohm; U/M: EA; Value: 150uF; TaMax_C: 125°C; SizeZ_mm: 14.5; SizeX_mm: 14.6; SizeY_mm: 13.6; Cap_Case: 12.5x13.5mm; SizeArea_mm2: 198.56; CompType: Capacitor; Cap_F: 150µF; IRMS_A: 700mA; AEC Grade: 1; AEC Category: Q200
C503 C504 C509 = CMP-0009150-2: as C205 on sheet DC402A_GaN-stage
C505 = CMP-0119346-1: as C400 on sheet DC402A_AMCsensing
C506 = CMP-0007343-5: CAP, CERM, 1 uF, 25 V, +/- 10%, X5R, 0603; Manufacturer: MuRata; TaMin_C: -55°C; Polarized: N; SizeAreaWB_mm2: 4.68; Value1: Unknown; U/M: EA; Value: 1uF; TaMax_C: 85°C; SizeZ_mm: 1; SizeX_mm: 1.6; SizeY_mm: 0.8; SizeArea_mm2: 1.28; Cap_F: 1µF; AEC Category: Q200
C508 C513-C515 = CMP-0006837-4: as C204 on sheet DC402A_GaN-stage
C511 C512 = CMP-0123891-1: Chip Multilayer Ceramic Capacitors for General Purpose, 1206, 22uF, X7R, 15%, 20%, 16V; Manufacturer: Murata; AEC Qualified: No; Cap_F: 22µF; SizeZ_mm: 1.9mm; Value: 22µF
C516 C517 = CMP-0081454-1: CAP, CERM, 10 µF, 50 V,+/- 20%, X5R, 1206; Manufacturer: Wurth Elektronik; TaMin_C: -55°C; Polarized: N; SizeAreaWB_mm2: 10.92; U/M: EA; Value: 10uF; TaMax_C: 125°C; SizeZ_mm: 1.8; SizeX_mm: 3.2; SizeY_mm: 1.6; Cap_Case: 1206; SizeArea_mm2: 5.12; AEC Category: Q200
D500 = CMP-0085026-1: Diode, TVS, Bi, 64 V, 103 Vc, 400 W, 3.9 A, SMA (non-polarized); Manufacturer: Littelfuse; SizeY_mm: 2.575; SizeZ_mm: 2.65; AEC Category: Q101; Value1: 103V; Vbr_Min: 71.1V; SizeX_mm: 5.075; Vbr_Max: 78.6V; Ppk: 400W; AEC Qualified: N; Ipp: 3.9A; SizeAreaWB_mm2: 32.368125; SizeArea_mm2: 13.068125; RJA_CperW: 120
L500 = CMP-0098596-1: WE-HCM SMT High Current Flat Wire Inductor, size 1390, 0.2uH, 47.5A, 0.165mOhm; Manufacturer: Wurth Elektronik; Material: MnZn; Case/Size Code: 1390; Saturation Current: 46.8A; Self Resonant Frequency: 22MHz
L501 = CMP-0064659-1: Inductor, Shielded Drum Core, Ferrite, 33 uH, 1.15 A, 0.153 ohm, SMD; Manufacturer: Wurth Elektronik; Isat: 1.15A @ 10% inductance drop; Irms: 1.22A @ 40C rise; Green_Lifecycle: Active; SizeAreaWB_mm2: 86.49; DCR_ohm: 0.153; Green_REACh: Passed; Value: 33uH; Imax_A: 1.15A; SizeZ_mm: 3.2; SizeX_mm: 7.3; SizeArea_mm2: 53.29; Ind_H: 33µH; AEC Category: Q200
L502 = CMP-0101711-1: WE-MAIA SMT Power Inductor, size 3015, 4.7uH, 1.5A, 162mOhm; Manufacturer: Wurth Elektronik; Case/Size Code: 3015; DC Resistance: 141mOhm; Saturation Current: 2.8A; Self Resonant Frequency: 30MHz
Q500 = CMP-0001032-4: MOSFET, N-CH, 100 V, 180 A, DDPAK; Alternate Manufacturer: None; Manufacturer: STMicroelectronics; VdsMax_V: 100V; QgTyp_nC: 180; Value: 100V; SizeY_mm: 10.16; AEC Qualified: N; SizeX_mm: 15.245; Value2: 180 nC; IdsMax_A: 180A; SizeAreaWB_mm2: 209.6992; Vgs_V: 20V; ChMode: Enhancement; SizeZ_mm: 4.445; AEC Category: Q101; SizeArea_mm2: 154.8892
R500 = CMP-0021521-3: as R400 on sheet DC402A_AMCsensing
R501 = CMP-0083501-1: RES, 22 k, 5%, 0.5 W, 1210; Manufacturer: Yageo; Power_W: 500mW; TempCo: 100 ppm/C; SizeAreaWB_mm2: 14.7; Value_Code: 22k0; Value: 22k; EIA_Code: E24; SizeX_mm: 3.2; SizeY_mm: 2.5; SizeZ_mm: 1.35; Value2: 0.5W; SizeArea_mm2: 8; AEC Qualified: N; VDC_V: 200V; AEC Category: Q200
R502 = CMP-0021711-3: as R401 on sheet DC402A_AMCsensing
R503 R506 R509 R515 = CMP-0022735-5: RES, 100 k, 1%, 0.1 W, 0603; Manufacturer: Yageo; Power_W: 100mW; TempCo: 100 ppm/C; Value: 100k; EIA_Code: E96; SizeX_mm: 1.6; SizeY_mm: 0.8; SizeZ_mm: 1; Value2: 0.1W; SizeArea_mm2: 1.28; AEC Qualified: N; VDC_V: 75V; AEC Category: Q200; SizeAreaWB_mm2: 4.68
R504 R505 R508 R512 R514 = CMP-0086358-1: as R603 on sheet DC402A-RevA_Interface
R507 = CMP-0023098-5: RES, 40.2 k, 1%, 0.1 W, 0603; Manufacturer: Yageo; Power_W: 100mW; TempCo: 100 ppm/C; Value_Code: 40k2; Value: 40.2k; EIA_Code: E96; SizeX_mm: 1.6; SizeY_mm: 0.8; SizeZ_mm: 1; Value2: 0.1W; SizeArea_mm2: 1.28; AEC Qualified: N; VDC_V: 75V; AEC Category: Q200; SizeAreaWB_mm2: 4.68
R510 = CMP-0023228-5: RES, 64.9 k, 1%, 0.1 W, 0603; Manufacturer: Yageo; Power_W: 100mW; TempCo: 100 ppm/C; Value_Code: 64k9; Value: 64.9k; EIA_Code: E96; SizeX_mm: 1.6; SizeY_mm: 0.8; SizeZ_mm: 1; Value2: 0.1W; SizeArea_mm2: 1.28; AEC Qualified: N; VDC_V: 75V; AEC Category: Q200; SizeAreaWB_mm2: 4.68
R511 = CMP-0022746-5: as R600 on sheet DC402A-RevA_Interface
R513 = CMP-0023167-5: RES, 51.0 k, 1%, 0.1 W, 0603; Manufacturer: Yageo; Power_W: 100mW; TempCo: 100 ppm/C; Value_Code: 51k0; Value: 51.0k; Res_ohm: 51k; SizeX_mm: 1.6; SizeY_mm: 0.8; SizeZ_mm: 1; Value2: 0.1W; SizeArea_mm2: 1.28; AEC Qualified: N; VDC_V: 75V; AEC Category: Q200; SizeAreaWB_mm2: 4.68
R516 = CMP-0022923-5: RES, 22.1 k, 1%, 0.1 W, 0603; Manufacturer: Yageo; Power_W: 100mW; TempCo: 100 ppm/C; Value_Code: 22k1; Value: 22.1k; EIA_Code: E96; SizeX_mm: 1.6; SizeY_mm: 0.8; SizeZ_mm: 1; Value2: 0.1W; SizeArea_mm2: 1.28; AEC Qualified: N; VDC_V: 75V; AEC Category: Q200; SizeAreaWB_mm2: 4.68
TP500 TP501 = CMP-0078143-4: TEST POINT.  No entry in BOM.
U500 = CMP-0013281-4: Low Iq Always ON Smart Diode Controller, DBV0006A (SOT-23-6); Alternate PartNumber: LM74700QDBVTQ1; Manufacturer: Texas Instruments; SizeZ_mm: 1.45; SizeX_mm: 2.8; SizeY_mm: 2.9; SizeArea_mm2: 8.12; CompType: IC; SizeAreaWB_mm2: 14.82; AEC Category: Q200; AEC Qualified: Y
U501 = CMP-0096892-1: 4.2-V to 80-V, 1-A Synchronous Buck Converter with 40-µA IQ; Manufacturer: Texas Instruments; Output Type: AdjustableProgrammable; AEC Qualified: No; Output Voltage: 1-75V; Standoff Height: 0mm; Nominal Supply Current: 40uA; Number Of Outputs: 1; TJmax_C: +150°C; Switching Frequency: 200-2200kHz; Min Supply Voltage: 4.2V; Max Duty Cycle: 97%; Max Supply Voltage: 80V; SizeZ_mm: 1.7mm
U502 = CMP-0090796-2: SIMPLE SWITCHER 4-V to 36-V, 1-A Buck Converter in SOT-23-6 package; Manufacturer: Texas Instruments; TaMin_C: -40°C; Number Of Outputs: 1; AEC Grade: Grade 1; TJmax_C: +150°C; AEC Qualified: Yes; Min Supply Voltage: 4V; SizeZ_mm: 1.45mm; Switching Frequency: 2.1MHz; Max Supply Voltage: 36V; AEC Category: Q200; Output Type: AdjustableProgrammable; TaMax_C: +125°C; Nominal Supply Current: 80-90uA; CompType: IC; Standoff Height: 0mm; Max Duty Cycle: 98%; Output Voltage: 1-28V

## Sheet DC402A_Hardware.SchDoc
size 431 x 279 mm; Date: Not shown in title block; ApprovedBy: Not shown in title block; CheckedBy: Not shown in title block; Author: Not shown in title block; CompanyName: Not shown in title block; Engineer: Not shown in title block; Organization: Not shown in title block; Address1: Not shown in title block; Address2: Not shown in title block; Address3: Not shown in title block; Address4: Not shown in title block; DocumentNumber: 3; Revision: Use project parameter SCH_Rev; SheetNumber: 3; SheetTotal: 6; PageSetup: Record=PageOptions¦CenterHorizontal=True¦CenterVertical=True¦PrintScale=1.00¦XCorrection=1.00¦YCorrection=1.00¦PrintKind=0¦BorderSize=5000000¦LeftOffset=0¦BottomOffset=0¦Orientation=2¦PaperLength=1000¦PaperWidth=1000¦Scale=100¦PaperSource=15¦PrintQuality=600¦MediaType=1¦DitherType=10¦PaperKind=Letter¦PrintScaleMode=1
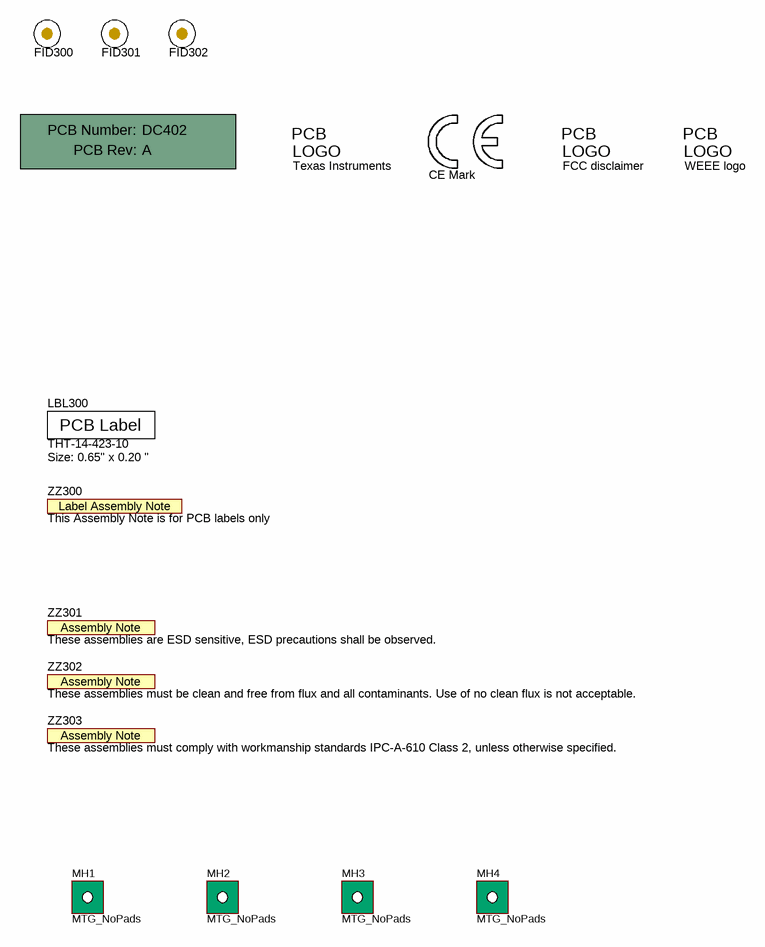
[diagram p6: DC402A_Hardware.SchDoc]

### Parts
!PCB300  Printed Circuit Board  (value not drawn)  (mechanical)
FID300  Fiducial  [Fiducial10-20]  (value not drawn)
FID301  Fiducial  [Fiducial10-20]  (value not drawn)
FID302  Fiducial  [Fiducial10-20]  (value not drawn)
LBL300  THT-14-423-10  Note: Size: 0.65" x 0.20 "  [Label_650x200]
Logo300  CE Mark  [CE_Mark_5mm]  (no BOM)
Logo301  Texas Instruments  [TI_Stacked_Overlay_Small]  (no BOM)
Logo302  FCC disclaimer  [FCC_disclaimer]  (no BOM)
Logo303  WEEE logo  [WEEE_Minimum]  (no BOM)
MH1  MTG_NoPads  [NPTH125mil]  (no BOM)
MH2  MTG_NoPads  [NPTH125mil]  (no BOM)
MH3  MTG_NoPads  [NPTH125mil]  (no BOM)
MH4  MTG_NoPads  [NPTH125mil]  (no BOM)
ZZ300  This Assembly Note is for PCB labels only  [AssemblyNoteLabel]  (no BOM)
ZZ301  These assemblies are ESD sensitive, ESD precautions shall be observed.  [AssemblyNote]  (no BOM)
ZZ302  These assemblies must be clean and free from flux and all contaminants. Use of no clean flux is not acceptable.  [AssemblyNote]  (no BOM)
ZZ303  These assemblies must comply with workmanship standards IPC-A-610 Class 2, unless otherwise specified.  [AssemblyNote]  (no BOM)

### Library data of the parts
!PCB300 = CMP-0003618-2: Manufacturer: Any; PartNumber: DC402
FID300-FID302 = CMP-0077181-1: Fiducial mark.  There is nothing to buy or mount.
LBL300 = CMP-0003625-1: Thermal Transfer Printable Labels, 0.650" W x 0.200" H - 10,000 per roll; Manufacturer: Brady; CompType: Label
Logo300 = CMP-0074844-1: SymbolCreator: a0412235
Logo301 = CMP-0074838-1: Texas Instrument Corporate Signature; SymbolCreator: a0412235; Lib Reference: TI_Logo; Library Reference: Logo
Logo302 = CMP-0074847-1: FCC_disclaimer; Library Reference: Logo
Logo303 = CMP-0074769-1
MH1-MH4 = CMP-0078424-2: PCB Mounting Hole, No Pad; Manufacturer: Any; Key: Mounting Hole (non-standard) No Pad
ZZ300 = CMP-0003616-3
ZZ301 = CMP-0077236-1
ZZ302 = CMP-0077237-1
ZZ303 = CMP-0077238-1

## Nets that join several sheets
DGND: DC402A (R1.2 R6.2), A (6 pins), CSA (7 pins), DC402A-RevA_Interface (18 pins), DC402_DCDC (17 pins), B (6 pins), CSB (7 pins), C (6 pins), CSC (7 pins)
P3V3: DC402A (R5.1), CSA (C401_CSA.1 C402_CSA.1 U400_CSA.8), DC402A-RevA_Interface (9 pins), DC402_DCDC (R512.1), CSB (C401_CSB.1 C402_CSB.1 U400_CSB.8), CSC (C401_CSC.1 C402_CSC.1 U400_CSC.8)
P5V: A (R200_A.1), DC402A-RevA_Interface (D605.2 R604.1 R616.2), DC402_DCDC (R505.1 R514.2), B (R200_B.1), C (R200_C.1)
PGND: DC402A (MP2.1 R1.1), A (11 pins), DC402_DCDC (8 pins), B (11 pins), C (11 pins)
VBUS: A (9 pins), DC402_DCDC (6 pins), B (9 pins), C (9 pins)
AVDD: A (R202_A.1), CSA (C404_CSA.1 C405_CSA.1 TP400_CSA.1 U400_CSA.1)
AVDD: B (R202_B.1), CSB (C404_CSB.1 C405_CSB.1 TP400_CSB.1 U400_CSB.1)
AVDD: C (R202_C.1), CSC (C404_CSC.1 C405_CSC.1 TP400_CSC.1 U400_CSC.1)
INN: DC402A (MP3.1 R2.2), CSA (R400_CSA.1 R402_CSA.2)
INN: DC402A (MP4.1 R3.2), CSB (R400_CSB.1 R402_CSB.2)
INN: DC402A (MP5.1 R4.2), CSC (R400_CSC.1 R402_CSC.2)
INP: DC402A (R2.1), A (C211_A.1 TP200_A.1 U200_A.5), CSA (6 pins)
INP: DC402A (R3.1), B (C211_B.1 TP200_B.1 U200_B.5), CSB (6 pins)
INP: DC402A (R4.1), C (C211_C.1 TP200_C.1 U200_C.5), CSC (6 pins)
MOD_CLK: DC402A (C1.1 C2.2), CSA (R404_CSA.1), DC402A-RevA_Interface (R621.2 U600.4), CSB (R404_CSB.1), CSC (R404_CSC.1)
MOD_D_phA: CSA (R405_CSA.1), DC402A-RevA_Interface (J601.12 R614.1)
MOD_D_phB: DC402A-RevA_Interface (J600.19 R613.2), CSB (R405_CSB.1)
MOD_D_phC: DC402A-RevA_Interface (J600.5), CSC (R405_CSC.1)
PWM_AH: A (R204_A.1), DC402A-RevA_Interface (J601.1 R600.1)
PWM_AL: A (R205_A.1), DC402A-RevA_Interface (J601.3 R601.1)
PWM_BH: DC402A-RevA_Interface (J601.5 R602.1), B (R204_B.1)
PWM_BL: DC402A-RevA_Interface (J601.7 R611.2), B (R205_B.1)
PWM_CH: DC402A-RevA_Interface (J601.9 R610.2), C (R204_C.1)
PWM_CL: DC402A-RevA_Interface (J601.11 R609.2), C (R205_C.1)
VCC48: DC402A (MP1.1), DC402_DCDC (7 pins)
VSNS_DC: DC402A-RevA_Interface (R605.2), DC402_DCDC (C505.2 R500.2 R502.2)
VSNS_phA: CSA (C400_CSA.2 R400_CSA.2 R401_CSA.2), DC402A-RevA_Interface (R606.2)
VSNS_phB: DC402A-RevA_Interface (R607.2), CSB (C400_CSB.2 R400_CSB.2 R401_CSB.2)
VSNS_phC: DC402A-RevA_Interface (R608.2), CSC (C400_CSC.2 R400_CSC.2 R401_CSC.2)

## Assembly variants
EVM-RELEASE: not fitted C211_A C211_B C211_C C503 D600 D601 D602 D603 R206_A R206_B R206_C R512 R514 R604 R617 R621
